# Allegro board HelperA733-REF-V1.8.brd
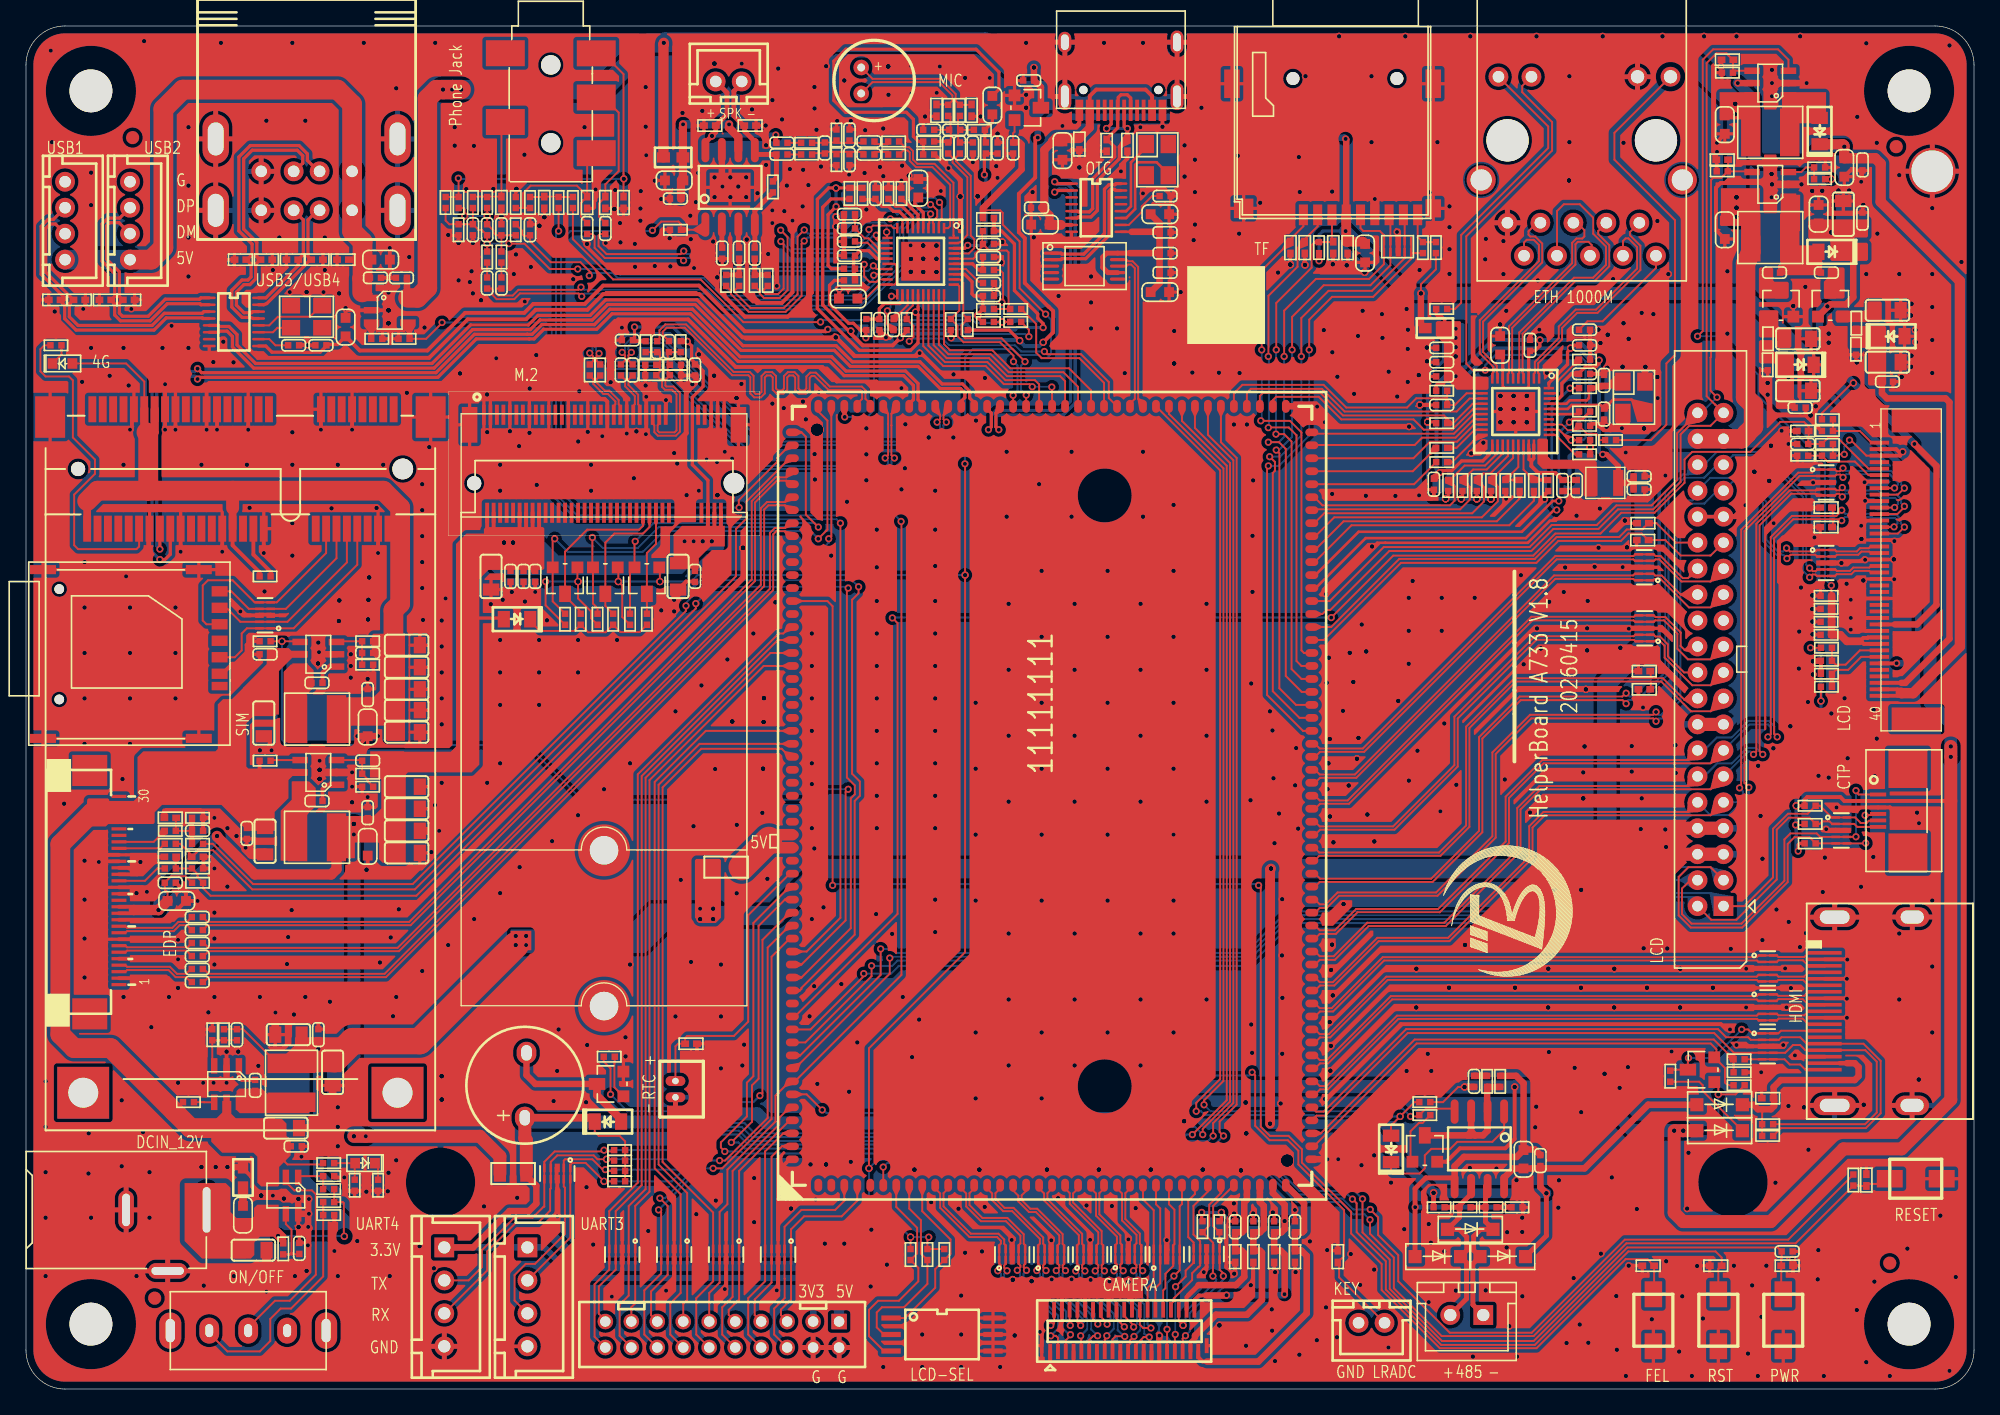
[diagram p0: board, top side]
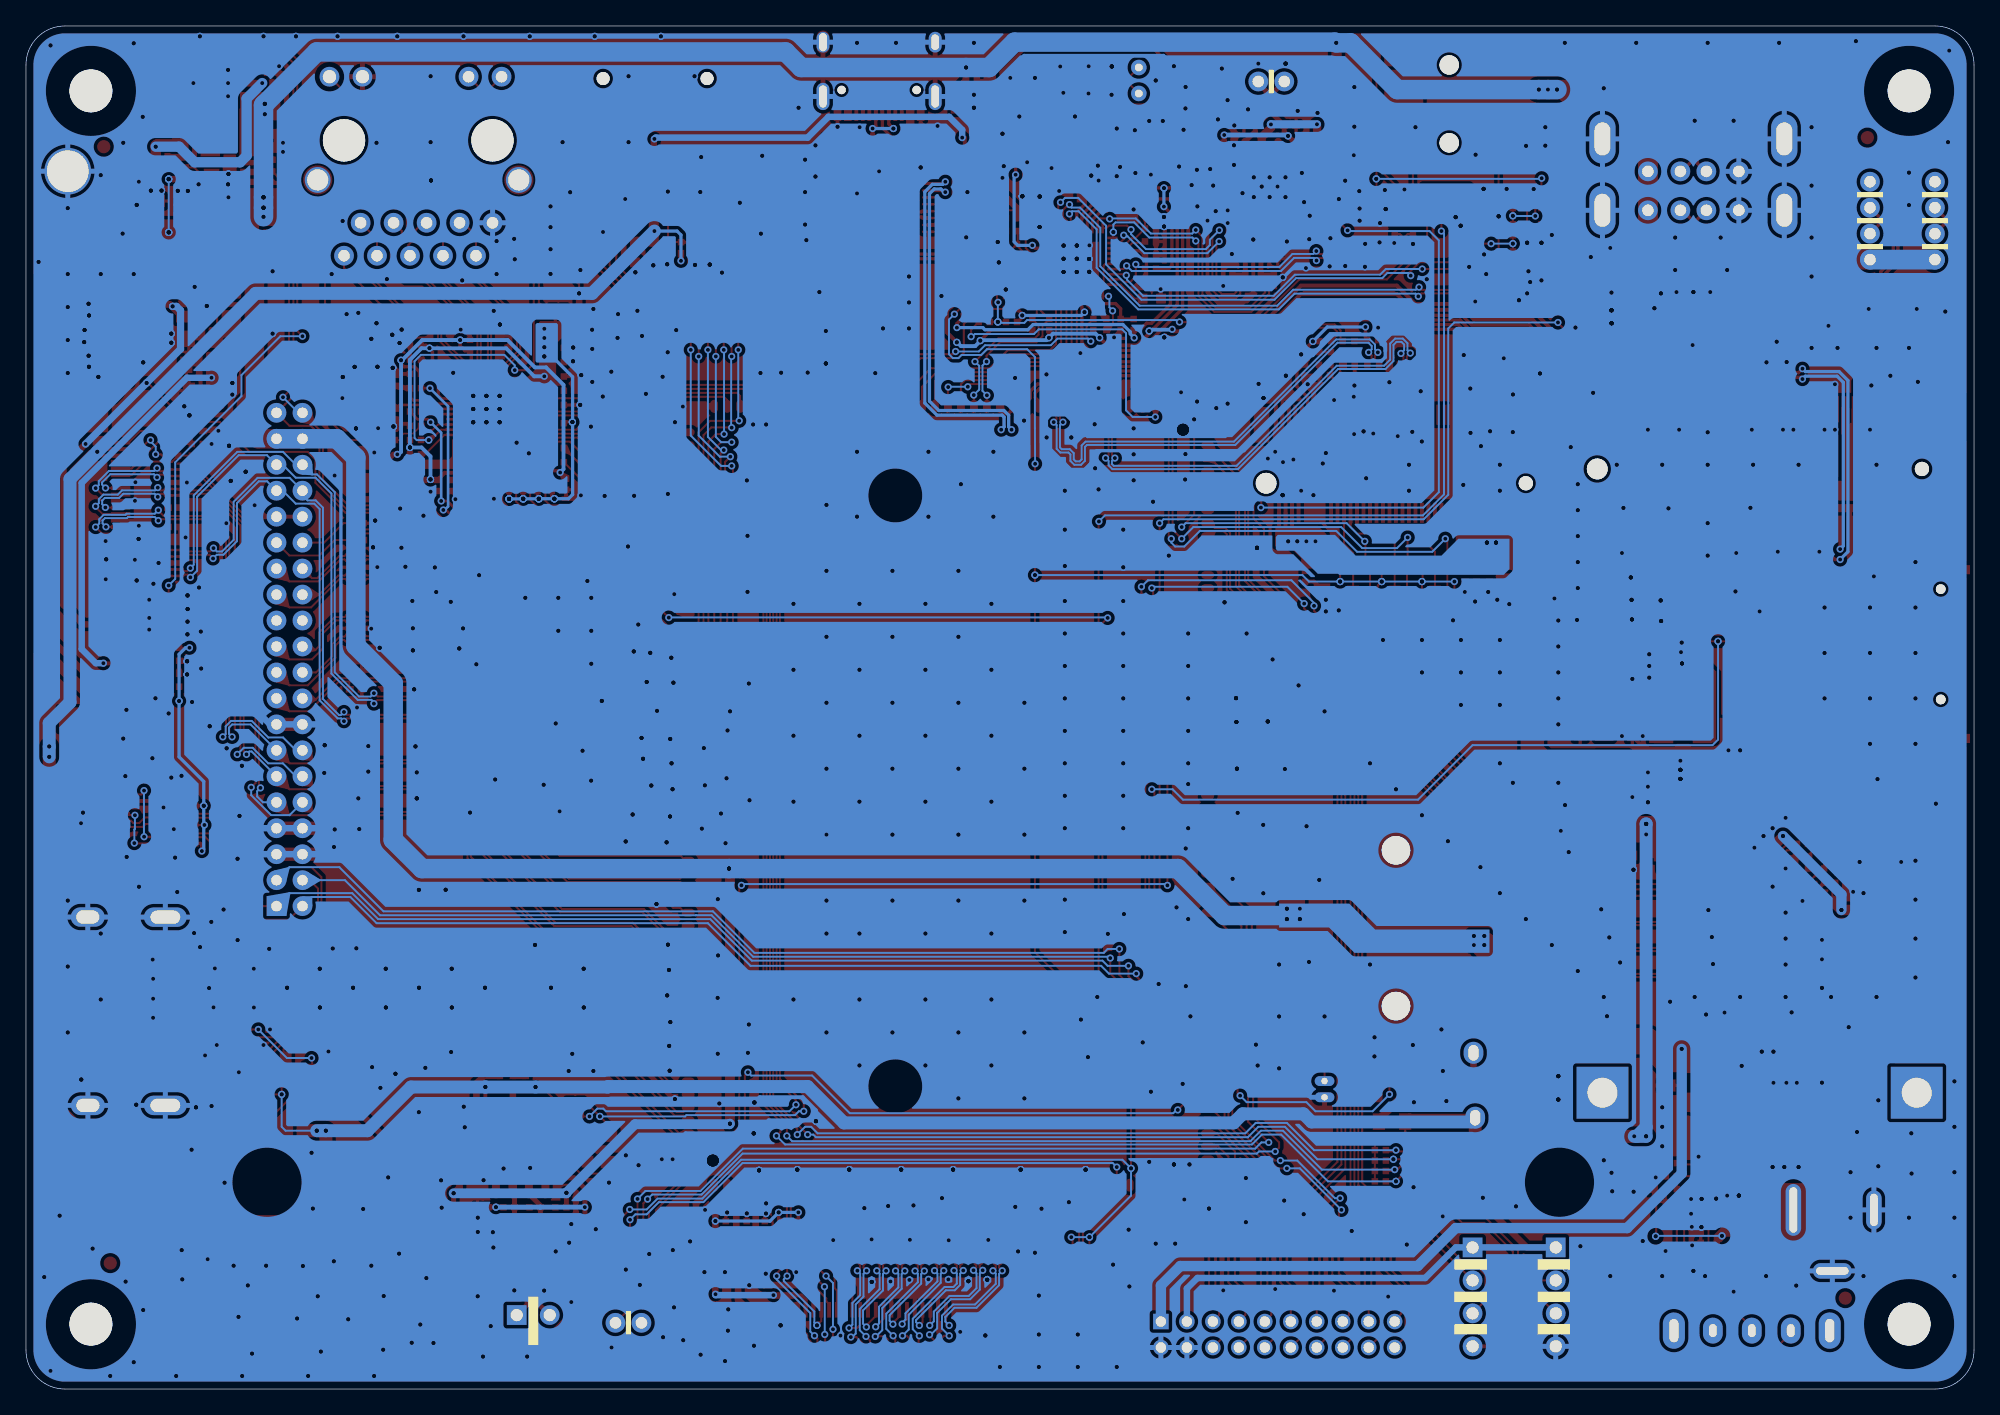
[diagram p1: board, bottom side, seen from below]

Outline 150 x 105 mm; copper layers: TOP, BOTTOM. Coordinates in mm from the lower left corner of the outline.
Outline path: 0,102 arc(0.88,104.12) 3,105 147,105 arc(149.12,104.12) 150,102 150,3 arc(149.12,0.88) 147,0 3,0 arc(0.88,0.88) 0,3 0,102

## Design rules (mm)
net group D1: nets PCIE1-RXN PCIE1-RXP
net group D2: nets N18105045 N18105047
net group D3: nets N18105049 N18105059
net group D4: nets N18105041 N18105043
net group D5: nets PCIE1-TXN PCIE1-TXP
net group D6: nets PCIE1-REFCLKN PCIE1-REFCLKP
net group D7: nets USB0-DM USB0-DP
net group D8: nets UPUSB-DM UPUSB-DP
net group D9: nets EDP-AUXN EDP-AUXP
net group D10: nets EDP-TX0N EDP-TX0P
net group D11: nets EDP-TX1N EDP-TX1P
net group D12: nets HTXCN HTXCP
net group D13: nets HTX2N HTX2P
net group D14: nets HTX1N HTX1P
net group D15: nets MICIN4N MICIN4P
net group D16: nets MCSIC-D1N MCSIC-D1P
net group D17: nets HTX0N HTX0P
net group D18: nets HUB1-DM3 HUB1-DP3
net group D19: nets MDI3+ MDI3-
net group D20: nets MDI2+ MDI2-
net group D21: nets MDI1+ MDI1-
net group D22: nets MDI0+ MDI0-
net group D23: nets MCSIC-D0N MCSIC-D0P
net group D24: nets MCSIC-CKN MCSIC-CKP
net group D25: nets MCSIA-D3N MCSIA-D3P
net group D26: nets MCSIA-D2N MCSIA-D2P
net group D27: nets MCSIA-D1N MCSIA-D1P
net group D28: nets MCSIA-D0N MCSIA-D0P
net group D29: nets MCSIA-CKN MCSIA-CKP
net group D30: nets LVDS1-D3N LVDS1-D3P
net group D31: nets LVDS1-D2N LVDS1-D2P
net group D32: nets LVDS1-D1N LVDS1-D1P
net group D33: nets LVDS1-D0N LVDS1-D0P
net group D34: nets LVDS1-CKN LVDS1-CKP
net group D35: nets LVDS0-D3N LVDS0-D3P
net group D36: nets LVDS0-D2N LVDS0-D2P
net group D37: nets LVDS0-D1N LVDS0-D1P
net group D38: nets LVDS0-D0N LVDS0-D0P
net group D39: nets LVDS0-CKN LVDS0-CKP

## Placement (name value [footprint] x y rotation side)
C1  .10  [C0402]  17.65 23.39 270 top
C2  .10  [C0805]  20.01 20.1 0 top
C3  .10  [C0402]  20.81 18.7 0 top
C4  .10  [C0402]  16.25 27.29 270 top
C5  .10  [C0805]  23.61 24.4 270 top
C6  .10  [C0805]  20.21 27.3 180 top
C7  .10  [C0402]  22.51 27.3 90 top
C8  .10  [C0402]  22.41 45.3 180 top
C9  .10  [C0805]  18.41 42.2 270 top
C10  .10  [C0402]  17.01 42.8 270 top
C11  .10  [C0402]  26.31 48.4 180 top
C12  .10  [C0402]  26.31 44.4 90 top
C13  .10  [C0603]  26.31 41.8 270 top
C19  .10  [C0402]  77.21 100.8 0 top
C20  .10  [C0402]  76.01 95.6 90 top
C21  .10  [C0402]  13.19 31.36 180 top
C22  .10  [C0402]  13.19 32.36 180 top
C23  .10  [C0402]  13.19 33.36 180 top
C24  .10  [C0402]  13.19 34.36 180 top
C25  .10  [C0402]  13.19 35.36 180 top
C26  .10  [C0402]  11.11 39 180 top
C27  .10  [C0603]  11.61 37.6 0 top
C28  .10  [C0402]  13.19 36.36 180 top
C29  .10  [C0402]  138.64 86 180 top
C30  .10  [C0805]  143.34 83.1 0 top
C31  .10  [C0402]  143.34 77.6 0 top
C32  .10  [C0805]  143.34 79.1 0 top
C33  .10  [C0402]  136.81 72.8 0 top
C34  .10  [C0805]  136.44 76.9 0 top
C35  .10  [C0402]  136.61 75.6 0 top
C36  .10  [C0402]  134.64 86 180 top
C37  .10  [C0805]  136.44 80.9 180 top
C38  .10  [C0603]  130.81 89.3 270 top
C39  .10  [C0805]  139.94 90.5 90 top
C40  .10  [C0402]  141.41 90.2 90 top
C41  .10  [C0603]  138.04 90.5 90 top
C42  .10  [C0603]  140.01 94.1 270 top
C43  .10  [C0402]  141.41 94.3 270 top
C44  .10  [C0603]  130.81 97.4 270 top
C45  .10  [C0603]  103.11 87.5 90 top
C46  .10  [C0402]  135.61 10.6 0 top
C47  .10  [C0402]  53.61 87.5 270 top
C48  .10  [C0402]  54.91 87.5 270 top
C49  .10  [C0402]  50.01 91.7 180 top
C50  .10  [C0402]  56.11 87.5 270 top
C51  .10  [C0603]  49.91 93.1 180 top
C52  .10  [C0402]  43.21 89.4 270 top
C53  .10  [C0402]  44.61 89.4 270 top
C54  .10  [C0402]  38.81 89.3 270 top
C55  .10  [C0402]  36.61 85.2 90 top
C56  .10  [C0402]  35.51 85.2 90 top
C57  .10  [C0402]  34.41 89.3 270 top
C58  .10  [C0402]  36.61 89.3 90 top
C59  .10  [C0603]  115.31 17.7 90 top
C60  .10  [C0402]  116.61 17.6 90 top
C61  .10  [C0402]  111.51 23.7 90 top
C62  .10  [C0402]  120.01 81.6 180 top
C63  .10  [C0603]  79.81 95.4 90 top
C64  .10  [C0402]  87.71 91.9 0 top
C65  .10  [C0402]  77.81 91 180 top
C66  .10  [C0603]  78.11 89.7 180 top
C67  .10  [C0402]  87.71 89.1 0 top
C68  .10  [C0603]  87.31 90.5 0 top
C69  .10  [C0402]  87.71 87.5 0 top
C70  .10  [C0402]  87.71 86 0 top
C71  .10  [C0603]  87.31 84.5 0 top
C84  .10  [C0603]  24.61 81.8 90 top
C86  .10  [C0402]  20.61 80.4 0 top
C87  .10  [C0402]  22.71 80.4 180 top
C88  .10  [C0805]  35.81 62.6 270 top
C89  .10  [C0402]  22.41 54.4 180 top
C90  .10  [C0805]  18.31 51.3 270 top
C91  .10  [C0402]  18.41 56.6 180 top
C92  .10  [C0402]  26.31 56.7 180 top
C93  .10  [C0402]  26.31 53.5 90 top
C94  .10  [C0603]  26.31 51 270 top
C95  .10  [C0805]  29.31 41.3 0 top
C96  .10  [C0805]  29.31 46.4 0 top
C97  .10  [C0805]  29.31 43 0 top
C98  .10  [C0805]  29.31 44.7 0 top
C99  .10  [C0805]  29.31 50.6 0 top
C100  .10  [C0805]  29.31 57.3 0 top
C101  .10  [C0805]  29.31 52.3 0 top
C102  .10  [C0805]  29.31 53.9 0 top
C103  .10  [C0805]  29.31 55.6 0 top
C322  .10  [C0603]  16.71 13.4 270 top
C323  .10  [C0402]  21.05 10.83 270 top
C324  .10  [C0805]  17.51 10.7 0 top
CA1  .10  [C0603]  68.71 92.5 270 top
CA2  .10  [C0402]  63.41 88.4 180 top
CA3  .10  [C0402]  63.41 90.5 0 top
CA4  .10  [C0402]  74.81 95.6 270 top
CA5  .10  [C0402]  72.91 95.6 90 top
CA6  .10  [C0402]  71.91 95.6 90 top
CA7  .10  [C0402]  71.51 97 180 top
CA8  .10  [C0603]  74.41 98.9 90 top
CA9  .10  [C0402]  71.01 95.6 90 top
CA10  .10  [C0402]  63.41 87.3 180 top
CA11  .10  [C0402]  74.11 87.2 0 top
CA12  .10  [C0402]  69.51 97 180 top
CA13  .10  [C0402]  65.71 82 270 top
CA14  .10  [C0402]  65.41 92.1 90 top
CA15  .10  [C0402]  74.11 88.2 0 top
CA16  .10  [C0402]  74.11 84.2 180 top
CA17  .10  [C0402]  74.11 85.2 0 top
CA18  .10  [C0603]  63.31 84 180 top
CA19  .10  [C0402]  66.81 82 270 top
CA20  .10  [C0402]  63.41 96.6 270 top
CA21  .10  [C0402]  64.91 96.1 0 top
CA22  .10  [C0402]  58.21 96 0 top
CA23  .10  [C0402]  61.51 95.6 270 top
CA24  .10  [C0402]  64.91 95.1 0 top
CA25  .10  [C0402]  58.21 95.1 0 top
CA26  .10  [C0402]  63.41 94.7 270 top
CA27  .10  [C0402]  35.51 89.3 270 top
CB1  .10  [C0402]  51.51 62.6 90 top
CB2  .10  [C0402]  37.31 62.6 90 top
CB3  .10  [C0805]  50.21 62.6 90 top
CB4  .10  [C0402]  46.71 78.5 270 top
CB5  .10  [C0402]  45.81 78.5 270 top
CB6  .10  [C0402]  39.21 62.6 90 top
CB7  .10  [C0402]  38.31 62.6 90 top
CB8  .10  [C0402]  51.51 78.5 90 top
CB9  .10  [C0402]  46.31 80.8 0 top
CB10  .10  [C0402]  48.61 80.3 270 top
CB11  .10  [C0402]  49.51 80.3 270 top
CE1  .10  [C0402]  120.01 78.2 180 top
CE2  .10  [C0402]  108.41 69.7 90 top
CE3  .10  [C0402]  124.21 70.3 180 top
CE4  .10  [C0603]  113.51 80.4 270 top
CE5  .10  [C0402]  115.81 80.4 270 top
CE6  .10  [C0402]  124.21 69.3 180 top
CE7  .10  [C0402]  109.01 75.8 0 top
CE8  .10  [C0402]  109.01 78 0 top
CE9  .10  [C0402]  120.01 80.4 180 top
CE10  .10  [C0402]  118.31 69.6 90 top
CE11  .10  [C0402]  109.01 80.2 0 top
CE12  .10  [C0402]  119.41 69.6 90 top
CE13  .10  [C0402]  109.01 79.1 0 top
CE14  .10  [C0402]  121.51 77.7 270 top
CE15  .10  [C0402]  121.51 75.1 90 top
CL1  .10  [C0402]  13.21 43 0 top
CON1  -  [FH35C-39S-0_3SHW]  84.56 4.4 0 top
CON2  -  [FPC30-0_5-1]  5.41 38.4 180 top
CON3  -  [MINI_PCIEX1-52P-5_2H]  16.51 44.7 180 top
CP1  .10  [C0402]  93.11 12.5 90 top
CP2  .10  [C0402]  94.51 12.5 90 top
CP3  .10  [C0402]  96.11 12.5 90 top
CP4  .10  [C0402]  97.71 12.5 90 top
CU1  .10  [C0402]  28.91 85.6 0 top
CU2  .10  [C0603]  27.31 87 180 top
CU3  .10  [C0402]  26.91 85.6 180 top
D2  .10  [D0603]  26.11 17.4 0 top
D3  -  [DFN2510-10_L2_5-W1_0-P0_50-BL]  78.94 10.36 0 top
D4  -  [DFN2510-10_L2_5-W1_0-P0_50-BL]  75.94 10.36 0 top
D5  -  [DFN2510-10_L2_5-W1_0-P0_50-BL]  81.94 10.36 0 top
D6  -  [DFN2510-10_L2_5-W1_0-P0_50-BL]  84.88 10.38 0 top
D7  -  [DFN2510-10_L2_5-W1_0-P0_50-BL]  87.84 10.36 0 top
D8  -  [DFN2510-10_L2_5-W1_0-P0_50-BL]  90.91 10.4 180 top
D9  .10  [ESD0402]  93.11 10.2 90 top
D10  .10  [ESD0402]  94.51 10.2 90 top
D11  .10  [ESD0402]  96.11 10.2 90 top
D12  .10  [ESD0402]  97.71 10.2 90 top
D13  -  [DFN2510-10_L2_5-W1_0-P0_50-BL]  138.61 69.83 270 top
D15  .10  [ESD0402]  11.11 41 0 top
D16  -  [DFN2510-10_L2_5-W1_0-P0_50-BL]  124.64 58.6 90 top
D17  .10  [ESD0402]  13.21 41 180 top
D18  .10  [ESD0402]  11.11 44 0 top
D19  -  [DFN2510-10_L2_5-W1_0-P0_50-BL]  124.61 63.3 90 top
D20  -  [DFN2510-10_L2_5-W1_0-P0_50-BL]  139.78 43.03 270 top
D21  -  [DFN2510-10_L2_5-W1_0-P0_50-BL]  138.61 63.63 270 top
D22  .10  [ESD0402]  130.61 94.7 180 top
D23  .10  [ESD0402]  131.01 102.4 180 top
D24  .10  [ESD0402]  124.51 66.7 180 top
D25  .10  [ESD0402]  124.49 65.4 180 top
D26  -  [SOT23]  138.94 83.6 0 top
D27  .10  [D0805]  143.64 81.1 180 top
D28  .10  [ESD0402]  136.81 73.8 180 top
D29  -  [SOT23]  135.14 83.6 0 top
D30  .10  [D0805]  136.64 78.9 0 top
D31  .10  [D0805]  139.04 87.6 0 top
D32  .10  [SOD323]  138.11 96.9 270 top
D33  .10  [ESD0402]  97.36 87.93 90 top
D34  .10  [ESD0402]  98.46 87.93 90 top
D35  .10  [ESD0402]  100.66 87.93 90 top
D36  .10  [ESD0402]  101.76 87.93 90 top
D37  .10  [ESD0402]  51.21 26.6 180 top
D38  -  [RCLAMP0524P]  105.61 88 180 top
D39  .10  [ESD0402]  124.91 9.5 180 top
D40  .10  [ESD0402]  130.11 9.5 0 top
D41  .10  [ESD0402]  135.61 9.5 180 top
D42  .10  [ESD0402]  141.71 16.1 90 top
D43  .10  [ESD0402]  101.01 10.2 270 top
D44  .10  [ESD0402]  55.76 97.33 180 top
D45  .10  [ESD0402]  52.66 97.33 0 top
D46  .10  [ESD0402]  46.01 91.4 90 top
D47  .10  [ESD0402]  36.61 91.4 90 top
D48  .10  [ESD0402]  43.21 91.4 90 top
D49  .10  [ESD0402]  39.91 91.4 90 top
D50  .10  [ESD0402]  44.61 91.4 90 top
D51  .10  [SOD323]  105.11 18.5 270 top
D52  .10  [SOD123]  113.71 10.2 0 top
D53  .10  [SOD123]  111.21 12.3 0 top
D54  .10  [SOD123]  108.71 10.2 0 top
D55  -  [DFN2510-10_L2_5-W1_0-P0_50-BL]  40.91 16.6 180 top
D56  .10  [SOD323]  44.81 20.6 180 top
D57  -  [DFN2510-10_L2_5-W1_0-P0_50-BL]  57.91 10.36 180 top
D58  -  [DFN2510-10_L2_5-W1_0-P0_50-BL]  53.91 10.36 180 top
D59  -  [DFN2510-10_L2_5-W1_0-P0_50-BL]  49.91 10.36 180 top
D60  -  [DFN2510-10_L2_5-W1_0-P0_50-BL]  45.91 10.36 180 top
D61  .10  [ESD0402]  84.81 95.8 270 top
D62  .10  [ESD0402]  83.21 95.8 270 top
D63  .10  [ESD0402]  81.11 95.9 270 top
D64  .10  [ESD0402]  24.41 87 0 top
D65  .10  [ESD0402]  22.41 87 0 top
D66  .10  [ESD0402]  20.51 87 180 top
D67  .10  [ESD0402]  16.51 87 180 top
D68  .10  [ESD0402]  18.51 87 0 top
D69  .10  [SOD123]  130.41 21.9 0 top
D70  .10  [SOD123]  130.41 19.9 0 top
D71  .10  [ESD0402]  134.11 22.4 180 top
D72  -  [DFN2510-10_L2_5-W1_0-P0_50-BL]  18.41 59.6 90 top
D73  .10  [D0603]  2.81 79 180 top
D76  .10  [ESD0402]  7.91 83.9 0 top
D77  .10  [ESD0402]  6.11 83.9 180 top
D78  .10  [ESD0402]  4.11 83.9 0 top
D79  .10  [ESD0402]  2.21 83.9 180 top
D80  .10  [ESD0402]  138.61 67.9 180 top
D81  .10  [ESD0402]  138.61 66.4 180 top
D82  .10  [ESD0402]  124.61 53.9 180 top
D83  .10  [ESD0402]  124.61 55.3 180 top
D84  .10  [SOD323]  37.81 59.3 0 top
DA1  .10  [ESD0402]  70.11 98.5 90 top
DA2  .10  [ESD0402]  72.81 98.5 90 top
DE1  -  [DFN2510-10_L2_5-W1_0-P0_50-BL]  134.11 32.4 270 top
FB1  .10  [L0603]  50.61 94.9 180 top
FB2  .10  [L0603]  107.71 81.7 0 top
FID1  -  [MARK]  9.91 7 270 top
FID2  -  [MARK]  143.51 9.7 0 top
FID3  -  [MARK]  8.21 96.4 0 top
FID4  -  [MARK]  144.01 95.7 0 top
FID5  -  [DVE]  146.78 93.81 0 top
H1  -  [DVA]  145 100 0 top
H2  -  [DVA]  145 5 0 top
H3  -  [DVA]  5 100 0 top
H4  -  [DVA]  5 5 0 top
J1  -  [DC470]  7.71 13.8 0 top
J2  -  [SS-12F44_1P2T_]  17.11 4.5 180 top
J3  -  [HDR2X20_2_0]  130.71 37.2 90 top
J4  -  [FPC40-0_5MM-UP]  142.21 53.4 90 top
J5  -  [FPC_0_5_6P_DOWN]  142.61 45.8 270 top
J6  -  [SW-1_27-6P]  70.51 4.2 0 top
J7  -  [TF_PUSH1]  100.61 97.7 0 top
J8  .10  [MX1_25-2P]  50.01 23.1 90 top
J9  .10  [PH-2_0-2P]  104.61 5.1 180 top
J10  .10  [PH-2_0-2P]  53.11 100.72 0 top
J11  -  [PJ327F]  37.41 105 270 top
J12  -  [M_2-M-KEY]  44.51 71.3 0 top
J13  .10  [XH-2_54-2P]  112.21 5.7 180 top
J14  -  [XH-2_54-4P]  38.61 7.1 90 top
J15  -  [XH-2_54-4P]  32.21 7.1 90 top
J16  -  [PHD2_0-2X10]  53.61 4.2 0 top
J17  .10  [BEEP_9042]  38.41 23.4 90 top
J18  -  [HY911130A]  125.51 87.3 0 top
J19  -  [USB_C]  87.51 98.5 180 top
J20  -  [USB-2A-03]  25.11 90.8 180 top
J21  -  [NANO-SIM-7P]  8.01 56.6 270 top
J22  -  [PH-2_0-4P]  8.01 93 270 top
J23  -  [PH-2_0-4P]  3.01 93 270 top
K1  .10  [KEY_3X4]  125.31 5.3 270 top
K2  .10  [KEY_3X4]  135.31 5.3 90 top
K3  .10  [KEY_3X4]  130.31 5.3 90 top
K4  .10  [KEY_3X4]  145.51 16.2 0 top
L1  .10  [4018]  20.45 23.59 90 top
L2  .10  [4018]  22.41 42.5 0 top
L4  .10  [4018]  134.31 88.7 0 top
L5  .10  [4018]  134.31 96.8 0 top
L6  .10  [SML2520_1P2H_4]  121.61 69.8 270 top
L7  .10  [4018]  22.41 51.6 0 top
MIC1  .10  [MIC6050]  65.31 100.8 180 top
Q1  -  [SOT23]  107.71 18.5 0 top
Q2  -  [SOT23]  45.01 23.5 90 top
Q3  -  [SOT23]  129.01 24.6 90 top
Q9  -  [SOT23]  47.81 62.3 180 top
Q10  -  [SOT23]  44.61 62.3 180 top
Q11  -  [SOT23]  41.51 62.3 180 top
R3  .10  [R0805]  53.91 40.2 0 top
R4  .10  [R0402]  15.25 27.29 270 top
R5  .10  [R0402]  12.51 22.1 0 top
R6  .10  [R0402]  25.31 15.7 90 top
R7  .10  [R0402]  14.35 27.29 90 top
R9  .10  [R0402]  26.31 47.4 180 top
R11  .10  [R0402]  26.31 46.4 180 top
R15  .10  [R0402]  90.59 12.51 270 top
R16  .10  [R0402]  91.89 12.51 270 top
R17  .10  [R0402]  138.71 71.9 180 top
R18  .10  [R0402]  136.81 71.9 180 top
R19  .10  [R0402]  13.21 39 180 top
R20  .10  [R0402]  13.21 40.1 180 top
R21  .10  [R0402]  11.11 40.1 180 top
R22  .10  [R0402]  11.11 42 180 top
R23  .10  [R0402]  137.38 42.03 180 top
R24  .10  [R0402]  137.38 44.93 180 top
R25  .10  [R0402]  137.38 43.53 180 top
R26  .10  [R0402]  11.11 43 180 top
R27  .10  [R0402]  138.64 57.1 0 top
R28  .10  [R0402]  138.64 54.1 0 top
R29  .10  [R0402]  140.94 82.1 270 top
R30  .10  [R0402]  138.71 74.7 0 top
R31  .10  [R0402]  138.71 72.8 180 top
R32  .10  [R0402]  140.91 80.1 90 top
R33  .10  [R0402]  134.14 80.9 270 top
R34  .10  [R0402]  138.64 56.1 180 top
R35  .10  [R0402]  138.64 55.1 180 top
R36  .10  [R0402]  138.71 73.8 180 top
R37  .10  [R0402]  134.11 78.9 90 top
R39  .10  [R0402]  138.11 93.2 0 top
R41  .10  [R0402]  130.61 93.8 0 top
R42  .10  [R0402]  138.11 94.1 0 top
R43  .10  [R0402]  131.01 101.4 180 top
R44  .10  [R0402]  138.61 61.1 180 top
R45  .10  [R0402]  138.61 58.1 180 top
R46  .10  [R0402]  138.61 60.1 180 top
R47  .10  [R0402]  138.61 59.1 180 top
R48  .10  [R0402]  70.71 10.36 270 top
R49  .10  [R0402]  69.41 10.36 270 top
R50  .10  [R0402]  68.11 10.36 270 top
R51  .10  [R0402]  108.56 87.93 90 top
R52  .10  [R0402]  99.56 87.93 90 top
R53  .10  [R0402]  107.56 87.93 90 top
R54  .10  [R0402]  140.71 16.1 270 top
R55  .10  [R0402]  50.01 89.3 0 top
R56  .10  [R0402]  53.91 85.4 90 top
R57  .10  [R0402]  54.91 85.4 90 top
R58  .10  [R0402]  57.51 92.6 90 top
R59  .10  [R0402]  57.11 85.4 90 top
R60  .10  [R0402]  56.11 85.4 90 top
R61  .10  [R0402]  41.01 91.4 90 top
R62  .10  [R0402]  42.11 91.4 90 top
R63  .10  [R0402]  38.81 91.4 270 top
R64  .10  [R0402]  37.71 89.3 90 top
R65  .10  [R0402]  33.31 89.3 270 top
R66  .10  [R0402]  36.61 87.2 90 top
R67  .10  [R0402]  37.71 91.4 90 top
R68  .10  [R0402]  35.51 87.2 90 top
R69  .10  [R0402]  107.71 22.1 0 top
R70  .10  [R0402]  108.81 14 0 top
R71  .10  [R0402]  112.51 23.7 270 top
R72  .10  [R0402]  113.51 23.7 90 top
R73  .10  [R0402]  110.81 14 180 top
R74  .10  [R0402]  107.71 21.1 180 top
R75  .10  [R0402]  114.81 14 0 top
R76  .10  [R0402]  112.81 14 180 top
R77  .10  [R0402]  45.71 16.8 180 top
R78  .10  [R0402]  45.71 16 180 top
R79  .10  [R0402]  45.71 17.6 180 top
R80  .10  [R0402]  45.71 18.4 180 top
R81  .10  [R0402]  44.91 25.6 0 top
R82  .10  [R0402]  122.01 73.1 180 top
R83  .10  [R0402]  120.01 74.2 180 top
R84  .10  [R0402]  120.01 73.1 180 top
R85  .10  [R0402]  109.01 83.2 180 top
R86  .10  [R0402]  120.01 77.1 0 top
R87  .10  [R0402]  131.91 23.4 0 top
R88  .10  [R0402]  126.61 24.1 90 top
R89  .10  [R0402]  131.91 25.4 0 top
R90  .10  [R0402]  134.11 19.5 180 top
R91  .10  [R0402]  134.11 20.4 180 top
R92  .10  [R0402]  131.91 24.4 0 top
R100  .10  [R0402]  18.41 62.6 180 top
R101  .10  [R0402]  2.31 80.4 0 top
R116  .10  [R0402]  26.31 55.8 0 top
R117  .10  [R0402]  26.31 57.6 180 top
R118  .10  [R0402]  18.41 57.6 180 top
R119  .10  [R0805]  37.51 16.6 180 top
R120  .10  [R0402]  46.51 59.3 90 top
R156  .10  [R0603]  16.71 16.3 180 top
R157  .10  [R0402]  23.31 15.4 180 top
R158  .10  [R0402]  23.31 16.4 0 top
R159  .10  [R0402]  19.81 10.8 270 top
R228  .10  [R0402]  47.81 59.3 90 top
R229  .10  [R0402]  44.01 59.3 90 top
R230  .10  [R0402]  45.21 59.3 90 top
R231  .10  [R0402]  41.51 59.3 90 top
R232  .10  [R0402]  42.71 59.3 90 top
R233  .10  [R0402]  18.41 48.4 0 top
R234  .10  [R0402]  48.11 78.9 180 top
R235  .10  [R0402]  50.01 78.9 0 top
R236  .10  [R0402]  47.71 80.3 270 top
R237  .10  [R0402]  50.41 80.3 270 top
R238  .10  [R0402]  23.31 14.4 0 top
R239  .10  [R0402]  23.31 13.4 180 top
R240  .10  [R0402]  23.31 17.4 180 top
R241  .10  [R0402]  27.11 15.7 90 top
R242  .10  [R0402]  44.21 78.5 270 top
R243  .10  [R0402]  43.41 78.5 270 top
R333  .10  [R0402]  50.01 78.1 0 top
R334  .10  [R0402]  48.11 78.1 180 top
RA1  .10  [R0402]  73.91 95.6 270 top
RA2  .10  [C0402]  63.41 89.4 0 top
RA3  .10  [R0402]  73.41 97 180 top
RA4  .10  [R0402]  66.41 92.1 90 top
RA5  .10  [R0402]  71.91 98.5 270 top
RA6  .10  [R0402]  71.01 98.5 270 top
RA7  .10  [R0402]  63.41 85.4 0 top
RA8  .10  [R0402]  63.41 86.3 180 top
RA9  .10  [R0402]  76.21 82.2 0 top
RA10  .10  [R0402]  69.51 96.1 0 top
RA11  .10  [R0402]  74.11 86.2 0 top
RA12  .10  [R0402]  69.51 95.1 0 top
RA13  .10  [R0402]  74.11 82.2 0 top
RA14  .10  [R0402]  64.71 82 90 top
RA15  .10  [R0402]  64.41 92.1 270 top
RA16  .10  [R0402]  63.41 92.1 90 top
RA17  .10  [R0402]  74.11 83.2 180 top
RA18  .10  [R0402]  74.11 89.2 180 top
RA19  .10  [R0402]  76.21 83.2 0 top
RA20  .10  [R0402]  74.11 90.2 0 top
RA21  .10  [R0402]  66.81 96.1 0 top
RA22  .10  [R0402]  72.51 82 270 top
RA23  .10  [R0402]  71.21 82 270 top
RA24  .10  [R0402]  67.81 82 90 top
RA25  .10  [R0402]  66.81 95.1 0 top
RA26  .10  [R0402]  67.41 92.1 90 top
RA27  .10  [R0402]  62.41 96.6 90 top
RA28  .10  [R0402]  60.11 96 0 top
RA29  .10  [R0402]  60.11 95.1 0 top
RA30  .10  [R0402]  62.41 94.7 90 top
RA31  .10  [R0402]  33.31 91.4 90 top
RA32  .10  [R0402]  34.41 91.4 90 top
RE1  .10  [R0402]  120.01 72 180 top
RE2  .10  [R0402]  109.01 76.9 0 top
RE3  .10  [R0402]  109.01 74.4 0 top
RE4  .10  [R0402]  120.01 79.3 180 top
RE5  .10  [R0402]  110.61 69.6 270 top
RE6  .10  [R0402]  109.01 72.5 0 top
RE7  .10  [R0402]  109.01 71.4 0 top
RE8  .10  [R0402]  111.71 69.6 270 top
RE9  .10  [R0402]  112.81 69.6 270 top
RE10  .10  [R0402]  116.11 69.6 90 top
RE11  .10  [R0402]  115.01 69.6 90 top
RE12  .10  [R0402]  120.01 75.3 180 top
RE13  .10  [R0402]  109.51 69.6 270 top
RE14  .10  [R0402]  117.21 69.6 90 top
RE15  .10  [R0402]  113.91 69.6 90 top
RL1  .10  [R0402]  13.21 42 180 top
RL2  .10  [R0402]  13.21 44 180 top
RN1  .10  [R0402]  35.51 91.4 90 top
RN2  .10  [R0402]  32.31 91.4 90 top
RU1  .10  [R0402]  29.11 80.9 0 top
RU2  .10  [R0402]  27.01 80.9 180 top
U1  -  [HELPERA733D-2]  79.01 45.7 90 top
U2  -  [SOT23-6]  15.45 23.49 180 top
U3  -  [SOT23-6]  22.51 47.5 90 top
U5  -  [SOT23]  77.11 98.7 270 top
U6  -  [SOT23-5]  134.31 92.8 90 top
U7  -  [SOT23-6]  134.31 100.6 90 top
U8  -  [ESOP-8]  54.22 92.57 0 top
U9  -  [SO8NB]  111.91 18.5 180 top
U10  -  [QFN40]  114.71 75.3 0 top
U11  -  [SSOP16_SL2_1S]  82.41 91 0 top
U12  -  [MSOP-10]  81.51 86.5 0 top
U13  -  [SOT23-5]  28.01 83.1 270 top
U14  -  [HDMIQ]  138.51 29.1 90 top
U15  -  [DFN2510-10_L2_5-W1_0-P0_50-BL]  134.11 29.4 270 top
U16  -  [DFN2510-10_L2_5-W1_0-P0_50-BL]  134.11 26.4 270 top
U42  -  [SSOP16_SL2_1S]  16.01 82.2 0 top
U43  -  [SOT23-6]  22.51 56.6 90 top
U44  -  [SOT23-6]  20.01 14.9 180 top
UA1  -  [QFN40]  68.89 86.88 0 top
UNK#REFDES  -  []  113.91 37 90 top
UNK#REFDES#2  -  []  89.41 80.5 0 top
X1  -  [X3225]  123.81 76.4 270 top
X2  -  [X3225]  87.11 94.7 270 top
X3  -  [X3225]  21.61 82.6 180 top

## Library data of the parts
C1 C3 C4 C7 C8 C10-C12 C19-C26 C28 C29 C31 C33 C35 C36 C40 C43 C46-C50 C52-C58 C60-C62 C64 C65 C67 C69 C70 C86 C87 C89 C91-C93 C323 CA2-CA7 CA9-CA17 CA19-CA27 CB1 CB2 CB4-CB11 CE1-CE3 CE5-CE15 CL1 CP1-CP4 CU1 CU3 RA2 = C0402
C2 C5 C6 C9 C30 C32 C34 C37 C39 C88 C90 C95-C103 C324 CB3 = C0805
C13 C27 C38 C41 C42 C44 C45 C51 C59 C63 C66 C68 C71 C84 C94 C322 CA1 CA8 CA18 CE4 CU2 = C0603
CON1 = FH35C-39S-0_3SHW
CON2 = FPC30-0_5-1
CON3 = MINI_PCIEX1-52P-5_2H
D2 D73 = D0603
D3-D8 D13 D16 D19-D21 D55 D57-D60 D72 DE1 U15 U16 = DFN2510-10_L2_5-W1_0-P0_50-BL
D9-D12 D15 D17 D18 D22-D25 D28 D33-D37 D39-D50 D61-D68 D71 D76-D83 DA1 DA2 = ESD0402
D26 D29 Q1-Q3 Q9-Q11 U5 = SOT23
D27 D30 D31 = D0805
D32 D51 D56 D84 = SOD323
D38 = RCLAMP0524P
D52-D54 D69 D70 = SOD123
FB1 FB2 = L0603
FID1-FID4 = MARK
FID5 H1-H4 = DV: alternate symbols: (DV,DVA,DVB,DVBA,DVC,DVD,DVDA,DVDAA,DVE,DVF)
J1 = DC470
J2 = SS-12F44_1P2T_
J3 = HDR2X20_2_0: alternate symbols: (HDR2X20_2_0,HDR2X20_2_0-SHENOU)
J4 = FPC40-0_5MM-UP
J5 = FPC_0_5_6P_DOWN
J6 = SW-1_27-6P
J7 = TF_PUSH1
J8 = MX1_25-2P
J9 J10 = PH-2_0-2P
J11 = PJ327F
J12 = M_2-M-KEY
J13 = XH-2_54-2P
J14 J15 = XH-2_54-4P
J16 = PHD2_0-2X10
J17 = BEEP_9042
J18 = HY911130A
J19 = USB_C
J20 = USB-2A-03
J21 = NANO-SIM-7P
J22 J23 = PH-2_0-4P
K1-K4 = KEY_3X4
L1 L2 L4 L5 L7 = 4018
L6 = SML2520_1P2H_4
MIC1 = MIC6050
R3 R119 = R0805
R4-R7 R9 R11 R15-R37 R39 R41-R92 R100 R101 R116-R118 R120 R157-R159 R228-R243 R333 R334 RA1 RA3-RA32 RE1-RE15 RL1 RL2 RN1 RN2 RU1 RU2 = R0402
R156 = R0603
U1 = HELPERA733D-2
U2 U3 U7 U43 U44 = SOT23-6
U6 U13 = SOT23-5
U8 = ESOP-8
U9 = SO8: alternate symbols: (SO8-OPT,SO8NB,SO8WB)
U10 UA1 = QFN40
U11 U42 = SSOP16_SL2_1S
U12 = MSOP-10
U14 = HDMIQ
X1-X3 = X3225

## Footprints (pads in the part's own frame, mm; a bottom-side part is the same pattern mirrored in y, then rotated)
4018
  rect 1.5x3.7 smd: 1(-1.5,0) 2(1.5,0)
BEEP_9042
  oval 1.7x1.524 hole 1.2x0.8: 1(-2.5,0) 2(2.5,-0.13)
C0402
  rect 0.5x0.5 smd: 1(-0.425,0) 2(0.425,0)
C0603
  rect 0.76x0.76 smd: 1(-0.71,0) 2(0.71,0)
C0805
  rect 0.94x1.27 smd: 1(-1.016,0) 2(1.016,0)
D0603
  rect 0.762x0.813 smd: 1(-0.762,0) 2(0.762,0)
D0805
  rect 0.94x1.27 smd: 1(-1.016,0) 2(1.016,0)
DC470
  oval 1.2x4 hole 0.6x3.5: 1(6.2,0)
  oval 1.2x3 hole 0.6x2.5: 2(0,0)
  oval 3x1.2 hole 2.5x0.6: 3(3.2,-4.7)
DFN2510-10_L2_5-W1_0-P0_50-BL
  rect 0.2x0.665 smd: 1(-1,-0.433) 2(-0.5,-0.433) 4(0.5,-0.433) 5(1,-0.433) 6(1,0.433) 7(0.5,0.433) 9(-0.5,0.433) 10(-1,0.433)
  rect 0.4x0.665 smd: 3(0,-0.433) 8(0,0.433)
DVA
  round 3.3 hole 3.3 unplated: (0,0)
DVE
  round 3.6 hole 3.2: 1(0,0)
ESD0402
  rect 0.61x0.508 smd: 1(-0.457,0) 2(0.457,0)
ESOP-8
  oval 0.61x1.88 smd: 1(-1.905,-2.87) 2(-0.635,-2.87) 3(0.635,-2.87) 4(1.905,-2.87) 5(1.905,2.87) 6(0.635,2.87) 7(-0.635,2.87) 8(-1.905,2.87)
  rect 3.15x2.261 smd: 9(0,0)
FH35C-39S-0_3SHW
  rect 0.3x1.2 smd: 1(-5.7,-1.5) 2(-5.4,1.7) 3(-5.1,-1.5) 4(-4.8,1.7) 5(-4.5,-1.5) 6(-4.2,1.7) 7(-3.9,-1.5) 8(-3.6,1.7) 9(-3.3,-1.5) 10(-3,1.7) 11(-2.7,-1.5) 12(-2.4,1.7) 13(-2.1,-1.5) 14(-1.8,1.7) 15(-1.5,-1.5) 16(-1.2,1.7) 17(-0.9,-1.5) 18(-0.6,1.7) 19(-0.3,-1.5) 20(0,1.7) 21(0.3,-1.5) 22(0.6,1.7) 23(0.9,-1.5) 24(1.2,1.7) 25(1.5,-1.5) 26(1.8,1.7) 27(2.1,-1.5) 28(2.4,1.7) 29(2.7,-1.5) 30(3,1.7) 31(3.3,-1.5) 32(3.6,1.7) 33(3.9,-1.5) 34(4.2,1.7) 35(4.5,-1.5) 36(4.8,1.7) 37(5.1,-1.5) 38(5.4,1.7) 39(5.7,-1.5)
  rect 0.3x1.15 smd: 40(6.35,-1.062) 41(-6.35,-1.062)
FPC30-0_5-1
  rect 1.15x0.25 smd: 1(-1.75,7.25) 2(-1.75,6.75) 3(-1.75,6.25) 4(-1.75,5.75) 5(-1.75,5.25) 6(-1.75,4.75) 7(-1.75,4.25) 8(-1.75,3.75) 9(-1.75,3.25) 10(-1.75,2.75) 11(-1.75,2.25) 12(-1.75,1.75) 13(-1.75,1.25) 14(-1.75,0.75) 15(-1.75,0.25) 16(-1.75,-0.25) 17(-1.75,-0.75) 18(-1.75,-1.25) 19(-1.75,-1.75) 20(-1.75,-2.25) 21(-1.75,-2.75) 22(-1.75,-3.25) 23(-1.75,-3.75) 24(-1.75,-4.25) 25(-1.75,-4.75) 26(-1.75,-5.25) 27(-1.75,-5.75) 28(-1.75,-6.25) 29(-1.75,-6.75) 30(-1.75,-7.25)
  rect 2.7x2.4 smd: 31(0.5,-9.25) 32(0.5,9.5)
FPC40-0_5MM-UP
  rect 0.3x1.5 smd: 1(19.5,-0.5) 2(19,-0.5) 3(18.5,-0.5) 4(18,-0.5) 5(17.5,-0.5) 6(17,-0.5) 7(16.5,-0.5) 8(16,-0.5) 9(15.5,-0.5) 10(15,-0.5) 11(14.5,-0.5) 12(14,-0.5) 13(13.5,-0.5) 14(13,-0.5) 15(12.5,-0.5) 16(12,-0.5) 17(11.5,-0.5) 18(11,-0.5) 19(10.5,-0.5) 20(10,-0.5) 21(9.5,-0.5) 22(9,-0.5) 23(8.5,-0.5) 24(8,-0.5) 25(7.5,-0.5) 26(7,-0.5) 27(6.5,-0.5) 28(6,-0.5) 29(5.5,-0.5) 30(5,-0.5) 31(4.5,-0.5) 32(4,-0.5) 33(3.5,-0.5) 34(3,-0.5) 35(2.5,-0.5) 36(2,-0.5) 37(1.5,-0.5) 38(1,-0.5) 39(0.5,-0.5) 40(0,-0.5)
  rect 1.8x3.8 smd: 41(-1.796,-3.345) 42(21.191,-3.35)
FPC_0_5_6P_DOWN
  rect 0.3x1.25 smd: 1(0,0) 2(0.5,0) 3(1,0) 4(1.5,0) 5(2,0) 6(2.5,0)
  rect 3x3 smd: 7(-2,2.3) 8(4.5,2.3)
HDMIQ
  rect 0.28x2.6 smd: 1(4.5,0) 2(4,0) 3(3.5,0) 4(3,0) 5(2.5,0) 6(2,0) 7(1.5,0) 8(1,0) 9(0.5,0) 10(0,0) 11(-0.5,0) 12(-1,0) 13(-1.5,0) 14(-2,0) 15(-2.5,0) 16(-3,0) 17(-3.5,0) 18(-4,0) 19(-4.5,0)
  oval 1.5x3.3 hole 1.016x2.286: 20(-7.25,-0.76) 21(7.25,-0.76)
  oval 1.5x2.616 hole 1.016x1.778: 22(-7.25,-6.72) 23(7.26,-6.732)
HDR2X20_2_0
  rect 1.524x1.524 hole 0.813: 1(0,0)
  round 1.524 hole 0.813: 2(0,2) 3(2,0) 4(2,2) 5(4,0) 6(4,2) 7(6,0) 8(6,2) 9(8,0) 10(8,2) 11(10,0) 12(10,2) 13(12,0) 14(12,2) 15(14,0) 16(14,2) 17(16,0) 18(16,2) 19(18,0) 20(18,2) 21(20,0) 22(20,2) 23(22,0) 24(22,2) 25(24,0) 26(24,2) 27(26,0) 28(26,2) 29(28,0) 30(28,2) 31(30,0) 32(30,2) 33(32,0) 34(32,2) 35(34,0) 36(34,2) 37(36,0) 38(36,2) 39(38,0) 40(38,2)
HELPERA733D-2
  oval 1x0.6 smd: 1(-30,18) 2(-30,17) 3(-30,16) 4(-30,15) 5(-30,14) 6(-30,13) 7(-30,12) 8(-30,11) 9(-30,10) 10(-30,9) 11(-30,8) 12(-30,7) 13(-30,6) 14(-30,5) 15(-30,4) 16(-30,3) 17(-30,2) 18(-30,1) 19(-30,0) 20(-30,-1) 21(-30,-2) 22(-30,-3) 23(-30,-4) 24(-30,-5) 25(-30,-6) 26(-30,-7) 27(-30,-8) 28(-30,-9) 29(-30,-10) 30(-30,-11) 31(-30,-12) 32(-30,-13) 33(-30,-14) 34(-30,-15) 35(-30,-16) 36(-30,-17) 37(-30,-18) 95(30,-18) 96(30,-17) 97(30,-16) 98(30,-15) 99(30,-14) 100(30,-13) 101(30,-12) 102(30,-11) 103(30,-10) 104(30,-9) 105(30,-8) 106(30,-7) 107(30,-6) 108(30,-5) 109(30,-4) 110(30,-3) 111(30,-2) 112(30,-1) 113(30,0) 114(30,1) 115(30,2) 116(30,3) 117(30,4) 118(30,5) 119(30,6) 120(30,7) 121(30,8) 122(30,9) 123(30,10) 124(30,11) 125(30,12) 126(30,13) 127(30,14) 128(30,15) 129(30,16) 130(30,17) 131(30,18)
  oval 0.6x1 smd: 38(-28,-20) 39(-27,-20) 40(-26,-20) 41(-25,-20) 42(-24,-20) 43(-23,-20) 44(-22,-20) 45(-21,-20) 46(-20,-20) 47(-19,-20) 48(-18,-20) 49(-17,-20) 50(-16,-20) 51(-15,-20) 52(-14,-20) 53(-13,-20) 54(-12,-20) 55(-11,-20) 56(-10,-20) 57(-9,-20) 58(-8,-20) 59(-7,-20) 60(-6,-20) 61(-5,-20) 62(-4,-20) 63(-3,-20) 64(-2,-20) 65(-1,-20) 66(0,-20) 67(1,-20) 68(2,-20) 69(3,-20) 70(4,-20) 71(5,-20) 72(6,-20) 73(7,-20) 74(8,-20) 75(9,-20) 76(10,-20) 77(11,-20) 78(12,-20) 79(13,-20) 80(14,-20) 81(15,-20) 82(16,-20) 83(17,-20) 84(18,-20) 85(19,-20) 86(20,-20) 87(21,-20) 88(22,-20) 89(23,-20) 90(24,-20) 91(25,-20) 92(26,-20) 93(27,-20) 94(28,-20) 132(28,20) 133(27,20) 134(26,20) 135(25,20) 136(24,20) 137(23,20) 138(22,20) 139(21,20) 140(20,20) 141(19,20) 142(18,20) 143(17,20) 144(16,20) 145(15,20) 146(14,20) 147(13,20) 148(12,20) 149(11,20) 150(10,20) 151(9,20) 152(8,20) 153(7,20) 154(6,20) 155(5,20) 156(4,20) 157(3,20) 158(2,20) 159(1,20) 160(0,20) 161(-1,20) 162(-2,20) 163(-3,20) 164(-4,20) 165(-5,20) 166(-6,20) 167(-7,20) 168(-8,20) 169(-9,20) 170(-10,20) 171(-11,20) 172(-12,20) 173(-13,20) 174(-14,20) 175(-15,20) 176(-16,20) 177(-17,20) 178(-18,20) 179(-19,20) 180(-20,20) 181(-21,20) 182(-22,20) 183(-23,20) 184(-24,20) 185(-25,20) 186(-26,20) 187(-27,20) 188(-28,20)
  round 2 smd: 189(-3,-7.3) 190(-6,-8.2)
HY911130A
  round 1.524 hole 0.889: 1(0,0) 2(-1.28,2.54) 3(-2.54,0) 4(-3.82,2.54) 5(-5.08,0) 6(-6.36,2.54) 7(-7.62,0) 8(-8.9,2.54) 9(-10.16,0) 10(-11.44,2.54) 13(-9.59,13.79) 14(-12.13,13.79)
  round 1.524 hole 1.02: 11(1.12,13.79) 12(-1.42,13.79)
  round 2.25 hole 1.63: 15(2.03,5.84) 16(-13.46,5.84)
  round 3.25 hole 3.25: 17(0,8.89) 18(-11.43,8.89)
KEY_3X4
  rect 2x1.35 smd: 1(-2,0) 2(2,0)
L0603
  rect 1x0.8 smd: 1(0.025,0.025) 2(1.525,0.025)
M_2-M-KEY
  round 1.1 hole 1.1 unplated: (-10,-1.525)
  round 1.6 hole 1.6 unplated: (10,-1.525)
  rect 0.3x1.55 smd: 1(-9.25,3.75) 2(-9,-3.8) 3(-8.75,3.75) 4(-8.5,-3.8) 5(-8.25,3.75) 6(-8,-3.8) 7(-7.75,3.75) 8(-7.5,-3.8) 9(-7.25,3.75) 10(-7,-3.8) 11(-6.75,3.75) 12(-6.5,-3.8) 13(-6.25,3.75) 14(-6,-3.8) 15(-5.75,3.75) 16(-5.5,-3.8) 17(-5.25,3.75) 18(-5,-3.8) 19(-4.75,3.75) 20(-4.5,-3.8) 21(-4.25,3.75) 22(-4,-3.8) 23(-3.75,3.75) 24(-3.5,-3.8) 25(-3.25,3.75) 26(-3,-3.8) 27(-2.75,3.75) 28(-2.5,-3.8) 29(-2.25,3.75) 30(-2,-3.8) 31(-1.75,3.75) 32(-1.5,-3.8) 33(-1.25,3.75) 34(-1,-3.8) 35(-0.75,3.75) 36(-0.5,-3.8) 37(-0.25,3.75) 38(0,-3.8) 39(0.25,3.75) 40(0.5,-3.8) 41(0.75,3.75) 42(1,-3.8) 43(1.25,3.75) 44(1.5,-3.8) 45(1.75,3.75) 46(2,-3.8) 47(2.25,3.75) 48(2.5,-3.8) 49(2.75,3.75) 50(3,-3.8) 51(3.25,3.75) 52(3.5,-3.8) 53(3.75,3.75) 54(4,-3.8) 55(4.25,3.75) 56(4.5,-3.8) 57(4.75,3.75) 58(5,-3.8) 67(7.25,3.75) 68(7.5,-3.8) 69(7.75,3.75) 70(8,-3.8) 71(8.25,3.75) 72(8.5,-3.8) 73(8.75,3.75) 74(9,-3.8) 75(9.25,3.75)
  rect 1.2x2.75 smd: 76(-10.35,2.975) 77(10.35,2.975)
  round 4 hole 2.2: 78(0,-29.8) 79(0,-41.8)
MARK
  round 1.016 smd: 1(0,0)
MIC6050
  round 1.2 hole 0.6: 1(1,-1) 2(1,1)
MINI_PCIEX1-52P-5_2H
  rect 0.61x2.007 smd: 1(-11.8,-30.775) 2(-11.4,-21.575) 3(-11,-30.775) 4(-10.6,-21.575) 5(-10.2,-30.775) 6(-9.8,-21.575) 7(-9.4,-30.775) 8(-9,-21.575) 9(-8.6,-30.775) 10(-8.2,-21.575) 11(-7.8,-30.775) 12(-7.4,-21.575) 13(-7,-30.775) 14(-6.6,-21.575) 15(-6.2,-30.775) 16(-5.8,-21.575) 17(-2.2,-30.775) 18(-1.8,-21.575) 19(-1.4,-30.775) 20(-1,-21.575) 21(-0.6,-30.775) 22(-0.2,-21.575) 23(0.2,-30.775) 24(0.6,-21.575) 25(1,-30.775) 26(1.4,-21.575) 27(1.8,-30.775) 28(2.2,-21.575) 29(2.6,-30.775) 30(3,-21.575) 31(3.4,-30.775) 32(3.8,-21.575) 33(4.2,-30.775) 34(4.6,-21.575) 35(5,-30.775) 36(5.4,-21.575) 37(5.8,-30.775) 38(6.2,-21.575) 39(6.6,-30.775) 40(7,-21.575) 41(7.4,-30.775) 42(7.8,-21.575) 43(8.2,-30.775) 44(8.6,-21.575) 45(9,-30.775) 46(9.4,-21.575) 47(9.8,-30.775) 48(10.2,-21.575) 49(10.6,-30.775) 50(11,-21.575) 51(11.4,-30.775) 52(11.8,-21.575)
  round 1.6 hole 1.6: G1(-12.5,-26.175)
  round 1.092 hole 1.092: G2(12.5,-26.175)
  rect 2.311x3.2 smd: M1(-14.65,-30.175) M2(14.65,-30.175)
  rect 4x4 hole 2.3: _/2(-12.1,21.875) _/3(12.1,21.875)
MSOP-10
  oval 1.2x0.25 smd: 1(-2.55,1) 2(-2.55,0.5) 3(-2.55,0) 4(-2.55,-0.5) 5(-2.55,-1) 6(2.55,-1) 7(2.55,-0.5) 8(2.55,0) 9(2.55,0.5) 10(2.55,1)
MX1_25-2P
  oval 0.762x1.524 hole 0.5: 1(-0.625,0) 2(0.625,0)
NANO-SIM-7P
  round 0.75 hole 0.75 unplated: (-5.02,-5.449) (3.48,-5.449)
  rect 0.8x1.23 smd: 1(0.23,6.9) 2(-2.31,6.9) 3(-4.85,6.9) 5(1.5,6.9) 6(-1.04,6.9) 7(-3.58,6.9)
  rect 0.65x1.23 smd: 4(2.45,6.9)
  rect 0.7x2 smd: 8(-6.52,5.3) 9(6.48,5.3) 10(-6.52,-6.7) 11(6.48,-6.7)
PH-2_0-2P
  round 1.524 hole 0.889: 1(0,0) 2(2,0)
PH-2_0-4P
  round 1.524 hole 0.889: 1(0,0) 2(2,0) 3(4,0) 4(6,0)
PHD2_0-2X10
  rect 1.2x1.2 hole 0.8: 1(9,1)
  round 1.2 hole 0.8: 2(9,-1) 3(7,1) 4(7,-1) 5(5,1) 6(5,-1) 7(3,1) 8(3,-1) 9(1,1) 10(1,-1) 11(-1,1) 12(-1,-1) 13(-3,1) 14(-3,-1) 15(-5,1) 16(-5,-1) 17(-7,1) 18(-7,-1) 19(-9,1) 20(-9,-1)
PJ327F
  round 1.5 hole 1.5 unplated: (3,3) (9,3)
  rect 2x3 smd: 1(2.1,-0.5) 2(7.4,-0.5) 3(9.8,6.5) 4(5.51,6.5) 5(2.11,6.5)
QFN40
  rect 0.2x0.8 smd: 1(1.8,2.55) 2(1.4,2.55) 3(1,2.55) 4(0.6,2.55) 5(0.2,2.55) 6(-0.2,2.55) 7(-0.6,2.55) 8(-1,2.55) 9(-1.4,2.55) 10(-1.8,2.55) 21(-1.8,-2.55) 22(-1.4,-2.55) 23(-1,-2.55) 24(-0.6,-2.55) 25(-0.2,-2.55) 26(0.2,-2.55) 27(0.6,-2.55) 28(1,-2.55) 29(1.4,-2.55) 30(1.8,-2.55)
  rect 0.8x0.2 smd: 11(-2.55,1.8) 12(-2.55,1.4) 13(-2.55,1) 14(-2.55,0.6) 15(-2.55,0.2) 16(-2.55,-0.2) 17(-2.55,-0.6) 18(-2.55,-1) 19(-2.55,-1.4) 20(-2.55,-1.8) 31(2.55,-1.8) 32(2.55,-1.4) 33(2.55,-1) 34(2.55,-0.6) 35(2.55,-0.2) 36(2.55,0.2) 37(2.55,0.6) 38(2.55,1) 39(2.55,1.4) 40(2.55,1.8)
  rect 3x3 smd: 41(0,0)
R0402
  rect 0.5x0.5 smd: 1(-0.425,0) 2(0.425,0)
R0603
  rect 0.8x1 smd: 1(0,0.75) 2(0,-0.75)
R0805
  rect 0.94x1.27 smd: 1(-1.016,0) 2(1.016,0)
RCLAMP0524P
  rect 0.2x0.675 smd: 1(1.05,0.435) 2(0.55,0.435) 4(-0.55,0.435) 5(-1.05,0.435) 6(-1.05,-0.44) 7(-0.55,-0.44) 9(0.55,-0.44) 10(1.05,-0.44)
  rect 0.4x0.675 smd: 3(-0.05,0.435) 8(-0.05,-0.44)
SML2520_1P2H_4
  rect 2x0.8 smd: 1(0,-1) 2(0,1)
SO8NB
  oval 0.61x1.88 smd: 1(-1.905,-2.87) 2(-0.635,-2.87) 3(0.635,-2.87) 4(1.905,-2.87) 5(1.905,2.87) 6(0.635,2.87) 7(-0.635,2.87) 8(-1.905,2.87)
SOD123
  rect 1.016x1.016 smd: 1(-1.753,0) 2(1.753,0)
SOD323
  rect 0.94x1.27 smd: 1(-1.016,0) 2(1.016,0)
SOT23
  rect 0.914x0.914 smd: 1(-0.953,-0.991) 2(0.953,-0.991)
  rect 0.914x1.27 smd: 3(0,1.041)
SOT23-5
  rect 0.5x1.2 smd: 1(-0.95,-1.4) 2(0,-1.4) 3(0.95,-1.4) 4(0.95,1.4) 5(-0.95,1.4)
SOT23-6
  rect 0.5x1.2 smd: 1(-0.95,-1.4) 2(0,-1.4) 3(0.95,-1.4) 4(0.95,1.4) 5(0,1.4) 6(-0.95,1.4)
SS-12F44_1P2T_
  oval 1.524x2 hole 0.6x1: 1(-3,0) 2(0,0) 3(3,0)
  oval 1.7x2.8 hole 0.7x1.8: 4(-6,0) 5(6,0)
SSOP16_SL2_1S
  oval 1x0.2 smd: 1(-1.9,1.855) 2(-1.9,1.325) 3(-1.9,0.795) 4(-1.9,0.265) 5(-1.9,-0.265) 6(-1.9,-0.795) 7(-1.9,-1.325) 8(-1.9,-1.855) 9(1.9,-1.855) 10(1.9,-1.325) 11(1.9,-0.795) 12(1.9,-0.265) 13(1.9,0.265) 14(1.9,0.795) 15(1.9,1.325) 16(1.9,1.855)
SW-1_27-6P
  rect 1.5x0.4 smd: 1(-3.9,1.27) 2(-3.9,0) 3(-3.9,-1.27) 4(3.95,-1.27) 5(3.95,0) 6(3.95,1.27)
TF_PUSH1
  rect 0.7x1.6 smd: 1(-2.25,-7.25) 2(-1.15,-7.25) 3(-0.05,-7.25) 4(1.05,-7.25) 5(2.15,-7.25) 6(3.25,-7.25) 7(4.35,-7.25) 8(5.45,-7.25) 9(6.55,-7.25)
  rect 1.5x1.5 smd: 10(-6.85,-6.75)
  rect 1.2x1.4 smd: 11(7.75,-6.75)
  rect 1.2x2.2 smd: 12(7.75,2.85) 13(-7.75,2.85)
  round 1 hole 1: _(4.95,3.25) _/2(-3.05,3.25)
USB-2A-03
  round 1.524 hole 0.889: 1(0,0) 2(2.5,0) 3(4.5,0) 4(7,0) 5(0,-3) 6(2.5,-3) 7(4.5,-3) 8(7,-3)
  oval 2.032x3.81 hole 1.219x2.54: 9(-3.5,-5.5) 10(10.5,-5.5) 11(-3.5,0) 12(10.5,0)
USB_C
  round 0.65 hole 0.65 unplated: (0.31,-1.57) (6.09,-1.57)
  oval 1x2.1 hole 0.6x1.7: 13(-1.12,-1.07) 14(7.52,-1.07)
  oval 1x1.8 hole 0.6x1.4: 15(-1.12,-5.25)
  oval 1x1.6 hole 0.6x1.2: 16(7.52,-5.25)
  rect 0.6x1.64 smd: A1(0,0) A4(0.8,0) B1(6.4,0) B4(5.6,0)
  rect 0.3x1.64 smd: A5(1.95,0) A6(2.95,0) A7(3.45,0) A8(4.45,0) B5(4.95,0) B6(3.95,0) B7(2.45,0) B8(1.45,0)
X3225
  rect 1.4x1.2 smd: 1(-1.2,-0.85) 2(1.2,-0.85) 3(1.2,0.85) 4(-1.2,0.85)
XH-2_54-2P
  rect 1.524x1.524 hole 0.94: 1(0,0)
  round 1.524 hole 0.94: 2(2.54,0)
XH-2_54-4P
  rect 1.524x1.524 hole 0.94: 1(3.81,0)
  round 1.524 hole 0.94: 2(1.27,0) 3(-1.27,0) 4(-3.81,0)

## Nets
5V: C4.1 C5.1 C6.1 C7.1 C19.2 C38.1 C44.1 C59.1 C60.1 CU1.2 D52.2 D69.1 FB1.2 J3.37 J3.38 J16.1 L1.2 L4.1 L5.1 R3.1 R4.1 R70.1 U5.3 U6.5 U7.6 U9.8 U13.5
5V-IN: R3.2 U1.163 U1.164
12V-IN: C322.2 C324.1 J1.1 R157.1 R159.1 R238.2 U44.4
AVCC: D58.4 D58.7 J16.11 R61.1 U1.182
AVDD: C39.1 C40.1 C41.1 D26.1 D31.2 J4.29 R30.1 R39.2
AVDD10: CE1.2 CE2.2 CE3.2 CE4.2 CE5.2 CE6.2 L6.2 U10.3 U10.8 U10.21 U10.38
AVDD33: CE8.2 CE9.2 CE10.2 CE11.2 CE12.2 CE13.2 FB2.2 R84.1 R85.2 RE1.1 RE2.1 RE3.1 RE5.2 RE8.2 RE9.2 RE13.2 U10.11 U10.28 U10.29 U10.40
AVDD-CSI: CON1.38 CP3.1 D11.2 R15.1 R16.1 U1.36
DVDD-CSI: CON1.37 CP2.1 D10.2 U1.35
GND: C2.2 C3.2 C5.2 C6.2 C7.2 C9.2 C10.2 C12.2 C13.2 C19.1 C20.1 C26.1 C27.2 C30.2 C31.2 C32.2 C33.1 C34.2 C35.2 C37.1 C38.2 C39.2 C40.2 C41.2 C42.2 C43.2 C44.2 C45.1 C46.2 C47.2 C49.2 C51.2 C54.1 C57.2 C58.2 C62.1 C63.1 C64.2 C65.2 C66.2 C67.2 C68.2 C69.2 C70.2 C71.2 C84.2 C86.2 C87.2 C88.2 C90.2 C91.2 C93.2 C94.2 C95.2 C96.2 C97.2 C98.2 C99.2 C100.2 C101.2 C102.2 C103.2 C323.1 C324.2 CA1.1 CA2.2 CA3.1 CA4.1 CA5.1 CA10.2 CA11.2 CA12.2 CA13.2 CA14.2 CA15.2 CA16.1 CA17.2 CA18.2 CA20.1 CA26.2 CB1.1 CB2.1 CB3.1 CB6.1 CB7.1 CB8.1 CB9.1 CE1.1 CE2.1 CE3.1 CE4.1 CE5.1 CE6.1 CE7.1 CE8.1 CE9.1 CE10.1 CE11.1 CE12.1 CE13.1 CE14.1 CE15.1 CL1.2 CON1.1 CON1.4 CON1.7 CON1.10 CON1.13 CON1.16 CON1.19 CON1.22 CON1.25 CON1.27 CON1.29 CON1.40 CON1.41 CON2.2 CON2.5 CON2.8 CON2.11 CON2.15 CON2.16 CON2.18 CON2.19 CON2.20 CON2.21 CON3.4 CON3.9 CON3.15 CON3.18 CON3.21 CON3.26 CON3.27 CON3.29 CON3.34 CON3.35 CON3.37 CON3.40 CON3.43 CON3.M1 CON3.M2 CP1.2 CP2.2 CP3.2 CP4.2 CU1.1 CU2.1 CU3.1 D3.3 D3.8 D4.3 D4.8 D5.3 D5.8 D6.3 D6.8 D7.3 D7.8 D8.3 D8.8 D9.1 D10.1 D11.1 D12.1 D13.3 D13.8 D15.1 D16.3 D16.8 D17.1 D18.1 D19.3 D19.8 D20.3 D20.8 D21.3 D21.8 D22.2 D23.2 D24.2 D25.2 D27.1 D28.2 D29.2 D30.2 D33.1 D34.1 D35.1 D36.1 D37.1 D38.3 D38.8 D39.2 D40.1 D41.1 D42.2 D43.1 D44.1 D45.1 D46.1 D47.1 D48.1 D49.1 D50.1 D55.3 D55.8 D57.3 D57.8 D58.3 D58.8 D59.3 D59.8 D60.3 D60.8 D61.2 D62.2 D63.2 D64.1 D65.2 D66.2 D67.2 D68.2 D71.2 D72.3 D72.8 D76.2 D77.2 D78.2 D79.2 D80.2 D81.2 D82.2 D83.2 DA1.1 DA2.1 DE1.3 DE1.8 FID5.1 J1.2 J1.3 J3.5 J3.6 J3.7 J3.8 J3.15 J3.16 J3.23 J3.24 J3.31 J3.32 J4.7 J4.10 J4.13 J4.16 J4.19 J4.22 J4.25 J4.28 J4.30 J5.3 J6.4 J6.5 J6.6 J7.6 J7.10 J7.11 J7.12 J7.13 J8.1 J9.2 J12.1 J12.3 J12.9 J12.15 J12.21 J12.27 J12.33 J12.39 J12.45 J12.51 J12.57 J12.71 J12.73 J12.75 J12.76 J12.77 J14.4 J15.4 J16.2 J16.4 J18.10 J18.12 J19.13 J19.14 J19.15 J19.16 J19.A1 J19.B1 J20.4 J20.8 J20.9 J20.10 J20.11 J20.12 J21.5 J21.8 J21.9 J21.10 J21.11 J22.1 J23.1 K1.2 K2.1 K3.1 K4.2 Q2.2 R6.1 R7.2 R11.2 R18.2 R20.1 R32.1 R34.2 R35.2 R36.2 R37.1 R41.1 R42.2 R43.2 R44.2 R45.2 R46.2 R47.2 R55.1 R65.2 R67.2 R75.2 R83.1 R92.2 R116.2 R118.2 R156.2 R158.2 R234.2 R235.2 R239.1 R241.1 R333.2 R334.2 RA2.1 RA4.2 RA12.2 RA26.2 RA27.2 RA30.1 RE4.1 RE14.1 RE15.1 RL2.1 RU1.1 RU2.1 U1.38 U1.95 U1.158 U1.162 U1.165 U1.188 U1.189 U1.190 U2.2 U3.2 U5.1 U6.2 U7.2 U8.7 U8.9 U10.41 U11.8 U12.3 U13.2 U14.2 U14.5 U14.8 U14.11 U14.17 U14.20 U14.21 U14.22 U14.23 U15.3 U15.8 U16.3 U16.8 U42.8 U43.2 U44.6 UA1.41 X1.2 X1.4
GND_485: C59.2 C60.2 D54.1 R72.2 R75.1 R76.1 U9.5
VBUS1: CU2.2 CU3.2 D64.2 J20.1 J20.5 J22.4 J23.4 U13.1
VBUS-EN: RU1.2 U1.172 U13.4
VBUS-USB: C63.2 C65.1 C66.1 D63.1 J19.A4 J19.B4 U11.7
VCC-1V8: C20.2 Q9.1 Q10.1 Q11.1 R48.1 R49.1 R50.1 R54.1 R120.1 R229.1 R231.1 RA20.1 U5.2
VCC-3V3: C45.2 C61.1 C84.1 C87.1 D36.2 D56.2 D70.1 FB2.1 J4.2 J4.3 J5.2 J7.4 J14.1 J15.1 J16.3 J17.1 Q1.2 Q3.1 R17.1 R23.2 R24.2 R25.2 R27.1 R28.1 R31.1 R51.1 R52.1 R69.2 R77.1 R78.1 R79.1 R80.1 R87.2 R119.1 RA16.1 RA22.2 RA23.2 RA24.1 U42.9
VCC_4G: C92.1 C93.1 C94.1 C99.1 C100.1 C101.1 C102.1 C103.1 CON3.2 CON3.24 CON3.39 CON3.41 CON3.52 D73.1 L7.2 R100.2 R117.1
VPP/VCC: CA10.1 RA7.2 RA8.1 UA1.15
VRN/AGND: RA26.1 UA1.6
VRP/AVCC: CA1.2 UA1.5
4G-EN: R118.1 U1.173 U43.4
340_3V3: C67.1 C68.1 C69.1 C70.1 C71.1 U11.9 U12.7 U12.10
485_1+: D53.1 D54.2 J13.2 R70.2 R73.2 U9.6
485_1-: D52.1 D53.2 J13.1 R73.1 R76.2 U9.7
AECRN: CA24.2 RA25.1
AECRP: CA21.2 RA21.1
AFVCC-CSI: CON1.36 CP1.1 D9.2 U1.34
AGND/VRP: RA4.1 UA1.7
AP-RESET: D40.2 K3.2 U1.167
AVCC/VRA1: CA14.1 RA15.2 UA1.8
BL-PWMI: CL1.1 D18.2 R26.1 RL1.2 RL2.2
CLKOUT-125M: RE12.2 U10.35
CLKREQN: J12.52 Q10.3 R230.2
CODEC-AVCC: CA16.2 RA8.2 RA13.1 RA15.1 RA16.2 RA17.2 UA1.25 UA1.33
CODEC-CPVDD: RA7.1 RA14.1 RA18.1 RA20.2
CODEC-IRQ: RA24.2 U1.108 UA1.24
CODEC-RST: RA19.2 U1.109
CPVDD: CA13.1 RA14.2 UA1.22
CTP0-INT: D20.5 D20.6 J3.3 J5.4 R23.1 U1.180
CTP0-RST: D20.4 D20.7 J3.4 J5.1 U1.181
DC_EN: R5.2 U2.4
DCIN: C2.1 C3.1 C9.1 C10.1 C90.1 C91.1 CON2.26 CON2.27 CON2.28 CON2.29 R5.1 R233.1 R240.2 U2.5 U3.5 U43.5 U44.3
DM1: D78.1 J23.3 U42.3
DM2: D76.1 J22.3 U42.1
DM3: D65.1 J20.2 U42.15
DM4: D67.1 J20.6 U42.13
DP1: D79.1 J23.2 U42.4
DP2: D77.1 J22.2 U42.2
DP3: D66.1 J20.3 U42.16
DP4: D68.1 J20.7 U42.14
EDP-AUXN: C28.1 U1.135
EDP-AUXP: C25.1 U1.136
EDP-EN: D17.2 R22.1 U1.174
EDP-HPD: D15.2 R19.1 R20.2 R21.1 U1.134
EDP-PWM: RL1.1 U1.175
EDP-TX0N: C23.1 U1.138
EDP-TX0P: C24.1 U1.137
EDP-TX1N: C21.1 U1.140
EDP-TX1P: C22.1 U1.139
FEL: D39.1 K1.1 U1.145
GPADC4: D59.2 D59.9 J16.14 U1.155
GPADC5: D59.1 D59.10 J16.13 U1.156
GPADC6: D58.5 D58.6 J16.12 U1.157
HBIAS: C54.2 R64.2 UA1.2
HCEC: Q3.2 R87.1 U1.39
HDMI-5V: D69.2 D71.1 R90.2 R91.2 U14.18
HDMI-HCEC: Q3.3 R88.2 U14.13 U16.1 U16.10
HHPD: R89.1 R92.1 U1.40
HHPD1: R89.2 U14.19 U16.5 U16.6
HP-DET: R62.1 RA9.1 RA11.2 RA13.2
HP-DET-PE11: RA9.2 U1.129
HPOUTFB-1: D47.2 J11.2 RA32.2 RN1.2
HPOUTFB-2: C57.1 CA27.2 R65.1 R68.2 RA32.1 RN2.1 UA1.18
HPOUTL-2: C52.2 UA1.17
HPOUTR-2: C53.2 UA1.19
HS-MIC-1: D46.2 J11.5 RA31.2 RN2.2
HS-MIC-2: C58.1 CA27.1 R64.1 R66.2 RA31.1 RN1.1
HSCL: R90.1 U1.42 U14.15 U16.2 U16.9
HSDA: R91.1 U1.41 U14.16 U16.4 U16.7
HTX0N: U1.45 U14.9 U15.2 U15.9
HTX0P: U1.46 U14.7 U15.1 U15.10
HTX1N: DE1.5 DE1.6 U1.47 U14.6
HTX1P: DE1.4 DE1.7 U1.48 U14.4
HTX2N: DE1.2 DE1.9 U1.49 U14.3
HTX2P: DE1.1 DE1.10 U1.50 U14.1
HTXCN: U1.43 U14.12 U15.5 U15.6
HTXCP: U1.44 U14.10 U15.4 U15.7
HUB1-DM3: U11.15 U12.2
HUB1-DP3: U11.16 U12.1
I2S0-BCLK: U1.111 UA1.29
I2S0-DIN0: U1.114 UA1.27
I2S0-DOUT0: U1.113 UA1.26
I2S0-LRCK: U1.112 UA1.28
I2S0-MCLK: U1.110 UA1.30
INTB: RE1.2 U10.31
IO-RESET: D42.1 K4.1 R54.2 U1.6
IOVDD-CSI: CON1.39 CP4.1 D12.2 U1.37
LCD0-EN: D22.1 J3.40 R41.2 U1.81 U6.4
LCD0-HSYNC: D25.1 J3.29 U1.78
LCD0-PWM: D23.1 J3.39 R43.1 U1.80 U7.4
LCD0-VSYNC: D24.1 J3.30 U1.79
LCD-PE3: J6.3 R50.2 U1.7
LCD-PE4: J6.2 R49.2 U1.8
LCD-PE5: J6.1 R48.2 U1.9
LCD_LR: J4.33 R27.2 R34.1
LCD_RST-PL7: C33.2 D28.1 J4.5 R31.2 U1.177
LCD_UD: J4.34 R28.2 R35.1
LDOIN/RSTN: CA15.1 RA17.1 RA18.2 RA19.1 UA1.36
LED0_AD0: J18.13 R84.2 U10.32
LED1_AD1: R82.2 R83.2 U10.33
LED+: C42.1 C43.1 D32.2 J4.39 J4.40 U7.5
LED-: J4.31 J4.32 R44.1 R45.1 R46.1 R47.1 U7.3
LRADC0: D43.2 J9.1 U1.183
LVDS0-CKN: D21.1 D21.10 J3.34 J4.17 U1.58
LVDS0-CKP: D21.2 D21.9 J3.33 J4.18 U1.57
LVDS0-D0N: D13.2 D13.9 J3.10 J4.8 U1.52
LVDS0-D0P: D13.1 D13.10 J3.9 J4.9 U1.51
LVDS0-D1N: D13.5 D13.6 J3.12 J4.11 U1.54
LVDS0-D1P: D13.4 D13.7 J3.11 J4.12 U1.53
LVDS0-D2N: D81.1 J3.14 J4.14 U1.56
LVDS0-D2P: D80.1 J3.13 J4.15 U1.55
LVDS0-D3N: D21.4 D21.7 J3.36 J4.20 U1.60
LVDS0-D3P: D21.5 D21.6 J3.35 J4.21 U1.59
LVDS1-CKN: D19.2 D19.9 J3.26 U1.68
LVDS1-CKP: D19.1 D19.10 J3.25 U1.67
LVDS1-D0N: D83.1 J3.18 U1.62
LVDS1-D0P: D82.1 J3.17 U1.61
LVDS1-D1N: D16.2 D16.9 J3.20 U1.64
LVDS1-D1P: D16.1 D16.10 J3.19 U1.63
LVDS1-D2N: D16.5 D16.6 J3.22 U1.66
LVDS1-D2P: D16.4 D16.7 J3.21 U1.65
LVDS1-D3N: D19.5 D19.6 J3.28 U1.70
LVDS1-D3P: D19.4 D19.7 J3.27 U1.69
MBIAS: CA4.2 RA1.2 UA1.38
MCSI0-MCLK: CON1.26 D7.1 D7.10 U1.26
MCSI2-MCLK: CON1.28 D7.2 D7.9 U1.27
MCSI-RST-F: CON1.31 D7.5 D7.6 U1.29
MCSI-RST-R: CON1.32 D8.4 D8.7 U1.31
MCSI-SCK-TWI2: CON1.34 D8.2 D8.9 R15.2 U1.32
MCSI-SDA-TWI2: CON1.35 D8.1 D8.10 R16.2 U1.33
MCSI-STBY-F: CON1.30 D7.4 D7.7 U1.28
MCSI-STBY-R: CON1.33 D8.5 D8.6 U1.30
MCSIA-CKN: CON1.14 D5.1 D5.10 U1.18
MCSIA-CKP: CON1.15 D5.2 D5.9 U1.19
MCSIA-D0N: CON1.11 D3.4 D3.7 U1.16
MCSIA-D0P: CON1.12 D3.5 D3.6 U1.17
MCSIA-D1N: CON1.8 D3.1 D3.10 U1.14
MCSIA-D1P: CON1.9 D3.2 D3.9 U1.15
MCSIA-D2N: CON1.5 D4.4 D4.7 U1.12
MCSIA-D2P: CON1.6 D4.5 D4.6 U1.13
MCSIA-D3N: CON1.2 D4.1 D4.10 U1.10
MCSIA-D3P: CON1.3 D4.2 D4.9 U1.11
MCSIC-CKN: CON1.23 D6.4 D6.7 U1.24
MCSIC-CKP: CON1.24 D6.5 D6.6 U1.25
MCSIC-D0N: CON1.20 D6.1 D6.10 U1.22
MCSIC-D0P: CON1.21 D6.2 D6.9 U1.23
MCSIC-D1N: CON1.17 D5.4 D5.7 U1.20
MCSIC-D1P: CON1.18 D5.5 D5.6 U1.21
MDI0+: J18.2 U10.1
MDI0-: J18.3 U10.2
MDI1+: J18.4 U10.4
MDI1-: J18.7 U10.5
MDI2+: J18.5 U10.6
MDI2-: J18.6 U10.7
MDI3+: J18.8 U10.9
MDI3-: J18.9 U10.10
MIC2N: DA1.2 MIC1.2 RA6.1
MIC2N/MIC3N: CA9.1 UA1.39
MIC2P: DA2.2 MIC1.1 RA5.1
MIC2P/MIC3P: CA6.1 UA1.37
MICIN1N: RA25.2 UA1.1
MICIN1P: RA21.2 UA1.40
MICIN4N: C56.1 UA1.4
MICIN4P: C55.1 UA1.3
PA-SHDN-PE15: R55.2 U1.133 U8.1
PA-VDD: C49.1 C51.1 FB1.1 U8.6
PC2: D60.2 D60.9 J16.18 U1.149
PC3: D60.5 D60.6 J16.20 U1.147
PC4: D60.4 D60.7 J16.19 U1.148
PC12: D60.1 D60.10 J16.17 U1.150
PCIE1-REFCLKN: CB11.1 U1.128
PCIE1-REFCLKP: CB10.1 U1.127
PCIE1-RXN: R243.1 U1.126
PCIE1-RXP: R242.1 U1.125
PCIE1-TXN: CB5.1 U1.122
PCIE1-TXP: CB4.1 U1.121
PCIE-3V3: C11.1 C12.1 C13.1 C26.2 C27.1 C88.1 C95.1 C96.1 C97.1 C98.1 CB1.2 CB2.2 CB3.2 CB6.2 CB7.2 CB8.2 CB9.2 CON2.12 CON2.13 D84.1 J12.2 J12.4 J12.12 J12.14 J12.16 J12.18 J12.70 J12.72 J12.74 L2.2 R9.1 R19.2 R119.2 R236.1 R237.1
PCIE-CLKREQN: Q10.2 R229.2 U1.131
PCIE-PERSTN: Q11.2 R231.2 U1.130
PCIE-WAKEN: Q9.2 R120.2 U1.132
PERSTN: J12.50 Q11.3 R232.2
PHYRSTB: CE7.2 RE2.2 U1.99 U10.12
PK10: D57.5 D57.6 J16.8 U1.186
PK11: D57.4 D57.7 J16.7 U1.187
PK12: D58.2 D58.9 J16.10 U1.184
PK13: D58.1 D58.10 J16.9 U1.185
PK16: D57.2 D57.9 J16.6 U1.3
PK17: D57.1 D57.10 J16.5 U1.4
PL12: D59.5 D59.6 J16.16 U1.171
PL13: D59.4 D59.7 J16.15 U1.170
PM5-BEEP: R81.1 U1.169
PWRON: C46.1 D41.2 K2.2 U1.168
REFCLKN: CB11.2 J12.53 R235.1 R237.2 R333.1
REFCLKP: CB10.2 J12.55 R234.1 R236.2 R334.1
REGOUT: L6.1 U10.30
RGMII0-CLK-25M: R86.1 U1.82
RGMII0-CLKIN-125M: RE12.1 U1.83
RGMII0-MDC: U1.98 U10.13
RGMII0-MDIO: RE3.2 U1.97 U10.14
RGMII0-RXCK: RE10.1 U1.84
RGMII0-RXCTL: RE11.1 U1.85
RGMII0-RXD0: RE9.1 U1.86 U10.25
RGMII0-RXD1: RE8.1 U1.87 U10.24
RGMII0-RXD2: RE5.1 U1.88 U10.23
RGMII0-RXD3: RE13.1 U1.89 U10.22
RGMII0-TXCK: RE7.1 U1.90
RGMII0-TXCTL: RE6.1 U1.91
RGMII0-TXD0: U1.92 U10.18
RGMII0-TXD1: U1.93 U10.17
RGMII0-TXD2: U1.94 U10.16
RGMII0-TXD3: U1.96 U10.15
RSET: RE4.2 U10.39
RTC-IN: D37.2 J8.2 U1.166
RXC/PHYAD1: RE10.2 RE14.2 U10.27
RXCTL/PHYAD2: RE11.2 RE15.2 U10.26
S-TWI0-CTP0-SCK: D20.2 D20.9 J3.2 J5.6 R25.1 U1.178
S-TWI0-CTP0-SDA: D20.1 D20.10 J3.1 J5.5 R24.1 U1.179
SDC0-CLK: D38.1 D38.10 J7.5 U1.74
SDC0-CMD: D35.2 J7.3 R52.2 U1.75
SDC0-D0: D38.2 D38.9 J7.7 U1.73
SDC0-D1: D38.4 D38.7 J7.8 U1.72
SDC0-D2: D33.2 J7.1 U1.77
SDC0-D3: D34.2 J7.2 U1.76
SDC0-DET: D38.5 D38.6 R53.1 U1.71
SPKR+: CA22.1 D45.2 J10.1 U8.8
SPKR-: CA25.1 D44.2 J10.2 R58.2 U8.5
SPOLN: R59.1 UA1.12
SPOLP: R56.1 UA1.11
SPORN: R60.1 UA1.10
SPORP: R57.1 UA1.9
TRM-CTR: C62.2 J18.1
TWI8-SCK: RA22.1 U1.115 UA1.32
TWI8-SDA: RA23.1 U1.116 UA1.31
TXC: RE7.2 U10.20
TXCTL: RE6.2 U10.19
UART0-RX: U1.107 U12.8
UART0-TX: U1.106 U12.9
UART2-RX: D51.1 R69.1 U1.105
UART2-TX: R74.2 U1.104 U9.4
UART3-RX: D55.2 D55.9 J14.3 R77.2 U1.101
UART3-TX: D55.1 D55.10 J14.2 R78.2 U1.100
UART4-RX: D55.4 D55.7 J15.3 R79.2 U1.103
UART4-TX: D55.5 D55.6 J15.2 R80.2 U1.102
UPUSB-DM: D62.1 J19.A7 J19.B7 U11.5
UPUSB-DP: D61.1 J19.A6 J19.B6 U11.6
USB0-DM: U1.117 U11.1
USB0-DP: U1.118 U11.2
USB1-DM: U1.119 U42.5
USB1-DP: U1.120 U42.6
USB2-DM: CON3.36 U1.123
USB2-DP: CON3.38 U1.124
USIM_CLK: CON3.12 D72.4 D72.7 J21.3
USIM_DATA: CON3.10 D72.2 D72.9 J21.7
USIM_RST: CON3.14 D72.5 D72.6 J21.2
USIM_VCC: CON3.8 D72.1 D72.10 J21.1
VCOM: J4.1 R30.2 R36.1
VDD-CORE/HP-DET: CA11.1 RA11.1 UA1.35
VGH: C31.1 C32.1 D27.2 J4.38 R29.2 R32.2
VGL: C34.1 C35.1 D30.1 J4.35 R33.2 R37.2
VRA1/MIC2P: CA2.1 UA1.14
VRA2/MIC2N: CA3.2 RA2.2 UA1.13
W_DISABLE_N: CON3.20 R100.1
WAKEN: J12.54 Q9.3 R228.2
XTAL-25MIN: CE15.2 U10.36 X1.3
XTAL-25MOUT: CE14.2 R86.2 U10.37 X1.1
N39839: J7.9 R51.2 R53.2
N638326: J18.14 R85.1
N638520: J18.11 R82.1
N5679088: C1.2 L1.1 U2.6
N5679096: C1.1 U2.1
N5679154: C4.2 R4.2 R7.1 U2.3
N16925291: D32.1 L5.2 U7.1
N17131711: D70.2 R88.1
N17175777: Q1.3 R71.2 R72.1 U9.2 U9.3
N17175783: D51.2 U9.1
N17177143: C8.2 L2.1 U3.6
N17177153: C11.2 R9.2 R11.1 U3.3
N17255318: Q2.1 R81.2
N17255336: D56.1 J17.2 Q2.3
N17819196: CA18.1 UA1.16 UA1.20
N17819206: CA19.1 UA1.23
N17819214: CA19.2 UA1.21
N17819230: CA17.1 UA1.34
N17819689: CA5.2 CA6.2 CA7.1 RA3.2 RA5.2
N17819691: CA7.2 CA9.2 CA12.1 RA6.2 RA10.2
N17819723: CA8.2 RA10.1 RA12.1
N17819725: CA8.1 RA1.1 RA3.1
N17838408: C55.2 R66.1
N17838410: C56.2 R68.1
N17838457: C52.1 D48.2 J11.3 R63.2 R67.1
N17838500: C53.1 D50.2 J11.4
N17838683: D49.2 R61.2 R62.2 R63.1
N17845378: C48.2 R56.2 R57.2
N17845396: C50.2 R59.2 R60.2
N17845478: C48.1 U8.3
N17845505: C50.1 R58.1 U8.4
N17845570: C47.1 U8.2
N17874598: CA20.2 CA21.1 CA23.1 RA27.1 RA28.2
N17874616: CA23.2 CA24.1 CA26.1 RA29.2 RA30.2
N17874634: CA22.2 RA28.1
N17874636: CA25.2 RA29.1
N17914651: C29.2 C36.1 D31.1 L4.2 U6.1
N17914681: C29.1 D26.3
N17914691: C37.2 D29.1 R33.1
N17914697: R39.1 R42.1 U6.3
N17914762: C30.1 D26.2 R29.1
N17915278: J4.6 R17.2 R18.1
N17963617: RU2.2 U13.3
N17967469: U11.12 X2.1
N17967471: U11.11 X2.3
N17967477: C64.1 U11.10
N18037700: R233.2 U3.4
N18103307: CB4.2 J12.49
N18103321: CB5.2 J12.47
N18104730: CON2.17 R21.2
N18104732: CON2.22 R22.2
N18104734: CON2.23 R26.2
N18105041: C21.2 CON2.3
N18105043: C22.2 CON2.4
N18105045: C25.2 CON2.9
N18105047: C28.2 CON2.10
N18105049: C23.2 CON2.6
N18105059: C24.2 CON2.7
N18142204: CON3.42 R101.1
N18142206: D73.2 R101.2
N18142901: U42.12 X3.1
N18142903: U42.11 X3.3
N18142917: C86.1 U42.10
N18148334: C89.2 L7.1 U43.6
N18148344: C92.2 R116.1 R117.2 U43.3
N18193662: D84.2 R228.1 R230.1 R232.1
N18243800: R157.2 R158.1 U44.1
N18243874: C323.2 R159.2 U44.5
N18245140: J2.3 R238.1 R239.2
N18245142: J2.2 U44.2
N18248395: D2.1 R6.2 R240.1
N18249325: D2.2 R241.2
N18257684: J12.43 R242.2
N18257704: J12.41 R243.2
N171758202: Q1.1 R74.1
N171758280: C61.2 R71.1
N171771995: C8.1 U3.1
N179147341: C36.2 D29.3
N181483905: C89.1 U43.1
N182437470: C322.1 R156.1

Pads without a net: CON2 1 14 24 25 30 31 32; CON3 1 3 5 6 7 11 13 16 17 19 22 23 25 28 30 31 32 33 44 45 46 47 48 49 50 51 _/2 _/3 G1 G2; FID1 1; FID2 1; FID3 1; FID4 1; J2 1 4 5; J4 4 23 24 26 27 36 37 41 42; J5 7 8; J7 _ _/2; J11 1; J12 5 6 7 8 10 11 13 17 19 20 22 23 24 25 26 28 29 30 31 32 34 35 36 37 38 40 42 44 46 48 56 58 67 68 69 78 79; J18 15 16 17 18; J19 A5 A8 B5 B8; J21 4 6; U1 1 2 5 141 142 143 144 146 151 152 153 154 159 160 161 176; U10 34; U11 3 4 13 14; U12 4 5 6; U14 14; U42 7; X2 2 4; X3 2 4

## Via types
v1: diameter 0.559, hole 0.305, TOP to BOTTOM, 3276 vias
v2: diameter 1, hole 0.9, TOP to BOTTOM, 14 vias

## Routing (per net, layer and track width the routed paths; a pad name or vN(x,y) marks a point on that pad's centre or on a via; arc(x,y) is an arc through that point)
5V: length 432.3
  TOP w0.152: 29.34,84.86 29.41,84.79 U13.5 ; R4.1 C4.1 16.72,27.72 19.35,25.09 L1.2 ; v1(51.91,36.2) v1(52.91,36.2) ; v1(131.61,99) 131.61,99.5 131.76,99.65 U7.6
  TOP w0.254: 133.11,88.7 L4.1
  TOP w0.3: C19.2 77.61,100.8
  TOP w0.381: v1(117.07,15.08) 117.07,11.81 D52.2 ; R70.1 108.39,14.17 v1(108.39,15.12)
  TOP w0.5: 77.61,100.8 v1(77.61,101.8) ; U5.3 78.15,100.28 C19.2 ; U13.5 29.34,84.12 CU1.2
  TOP w0.508: U9.8 113.82,16.28 114.53,16.99 C59.1 116.01,16.99 116.02,17 116.61,17 ; 116.61,17 116.61,15.54 v1(117.07,15.08) ; 116.61,17 120.01,17 124.91,21.9 D69.1 ; 116.43,16.99 116.61,17.18
  TOP w0.762: v1(95.8,20.44) 95.8,40.02 v1(95.87,40.09)
  TOP w0.8: v1(49.11,103.7) 49.11,103.6 49.09,103.57 FB1.2
  TOP w1.5: U13.5 30.15,84.05 30.91,84.81 30.91,99.4 31.61,100.1 v1(32.11,100.1) v1(32.81,100.1) v1(33.51,100.1) ; J3.38 J3.37 132.12,73.2 132.49,73.57 132.49,73.61 133.02,74.14 133.02,75.79 132.41,76.4 132.41,86.7 132.81,87.6 L4.1
  TOP w2.032: v1(37.71,34.2) 30.31,26.8 25.16,26.8 23.78,25.42 C5.1
  BOTTOM w0.152: v1(131.71,91.8) 131.91,91.8 131.91,91.1 131.81,91.1 v1(131.71,91) ; v1(52.91,37) v1(52.91,36.2) v1(51.91,37) ; v1(131.61,99) v1(131.61,98.2)
  BOTTOM w0.762: v1(117.07,15.08) 108.39,15.08 v1(108.39,15.12) 103.1,20.4 95.84,20.4 v1(95.8,20.44)
  BOTTOM w0.8: J16.1 62.61,7.98 61.12,9.47 42.84,9.47 39.91,12.4 26.71,12.4 22.51,16.6 v1(22.51,26.2)
  BOTTOM w1.5: 52.76,36.48 57.71,36.48 61.31,40.09 v1(95.87,40.09) 119.51,40.09 121.72,42.3 121.72,54.38 124.6,57.26 124.6,71.74 126.06,73.2 J3.38 J3.37 ; v1(131.71,90.3) v1(131.71,91) v1(131.71,91.8) 131.71,98.9 v1(131.61,99) 127.61,103 91.51,103 90.31,101.8 v1(77.61,101.8) 75.83,101.8 73.88,103.75 49.21,103.75 v1(49.11,103.7) 48.01,103.7 44.41,100.1 v1(33.51,100.1) v1(32.81,100.1) v1(32.11,100.1)
  vias: v1(37.71,34.9) v1(37.71,34.9) v1(38.51,34.9) v1(38.51,34.9) v1(38.51,34.2)
